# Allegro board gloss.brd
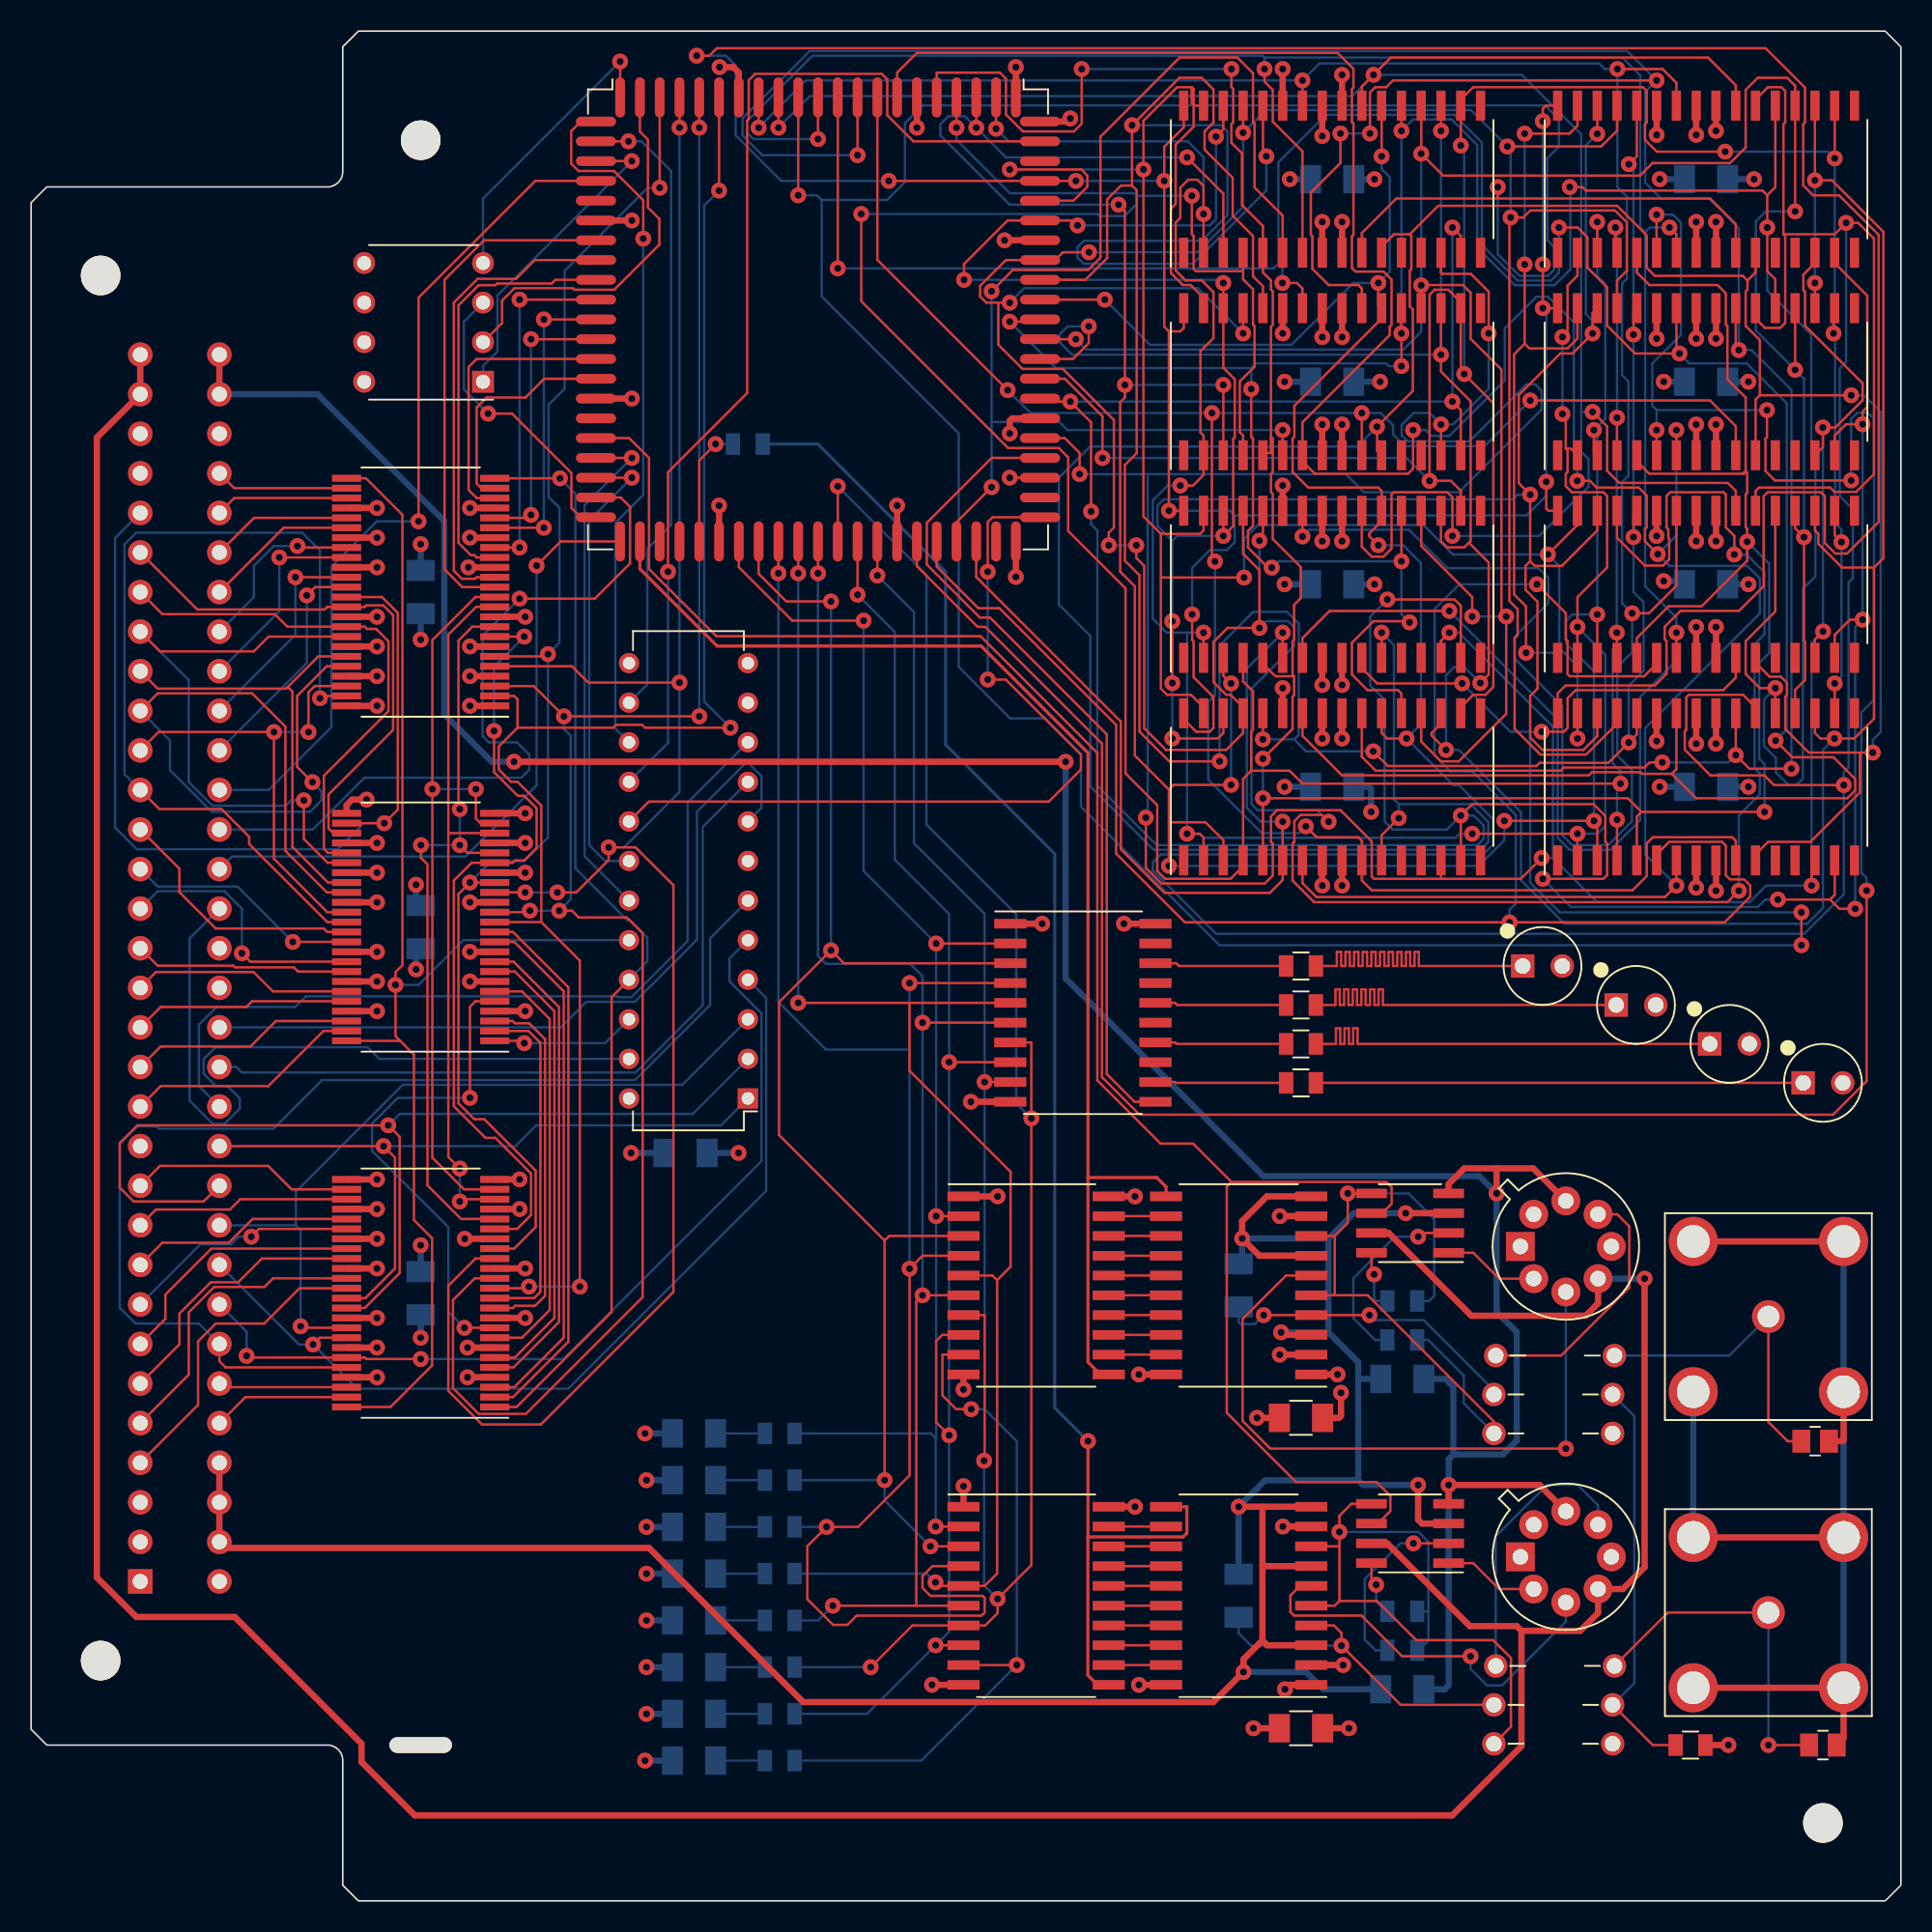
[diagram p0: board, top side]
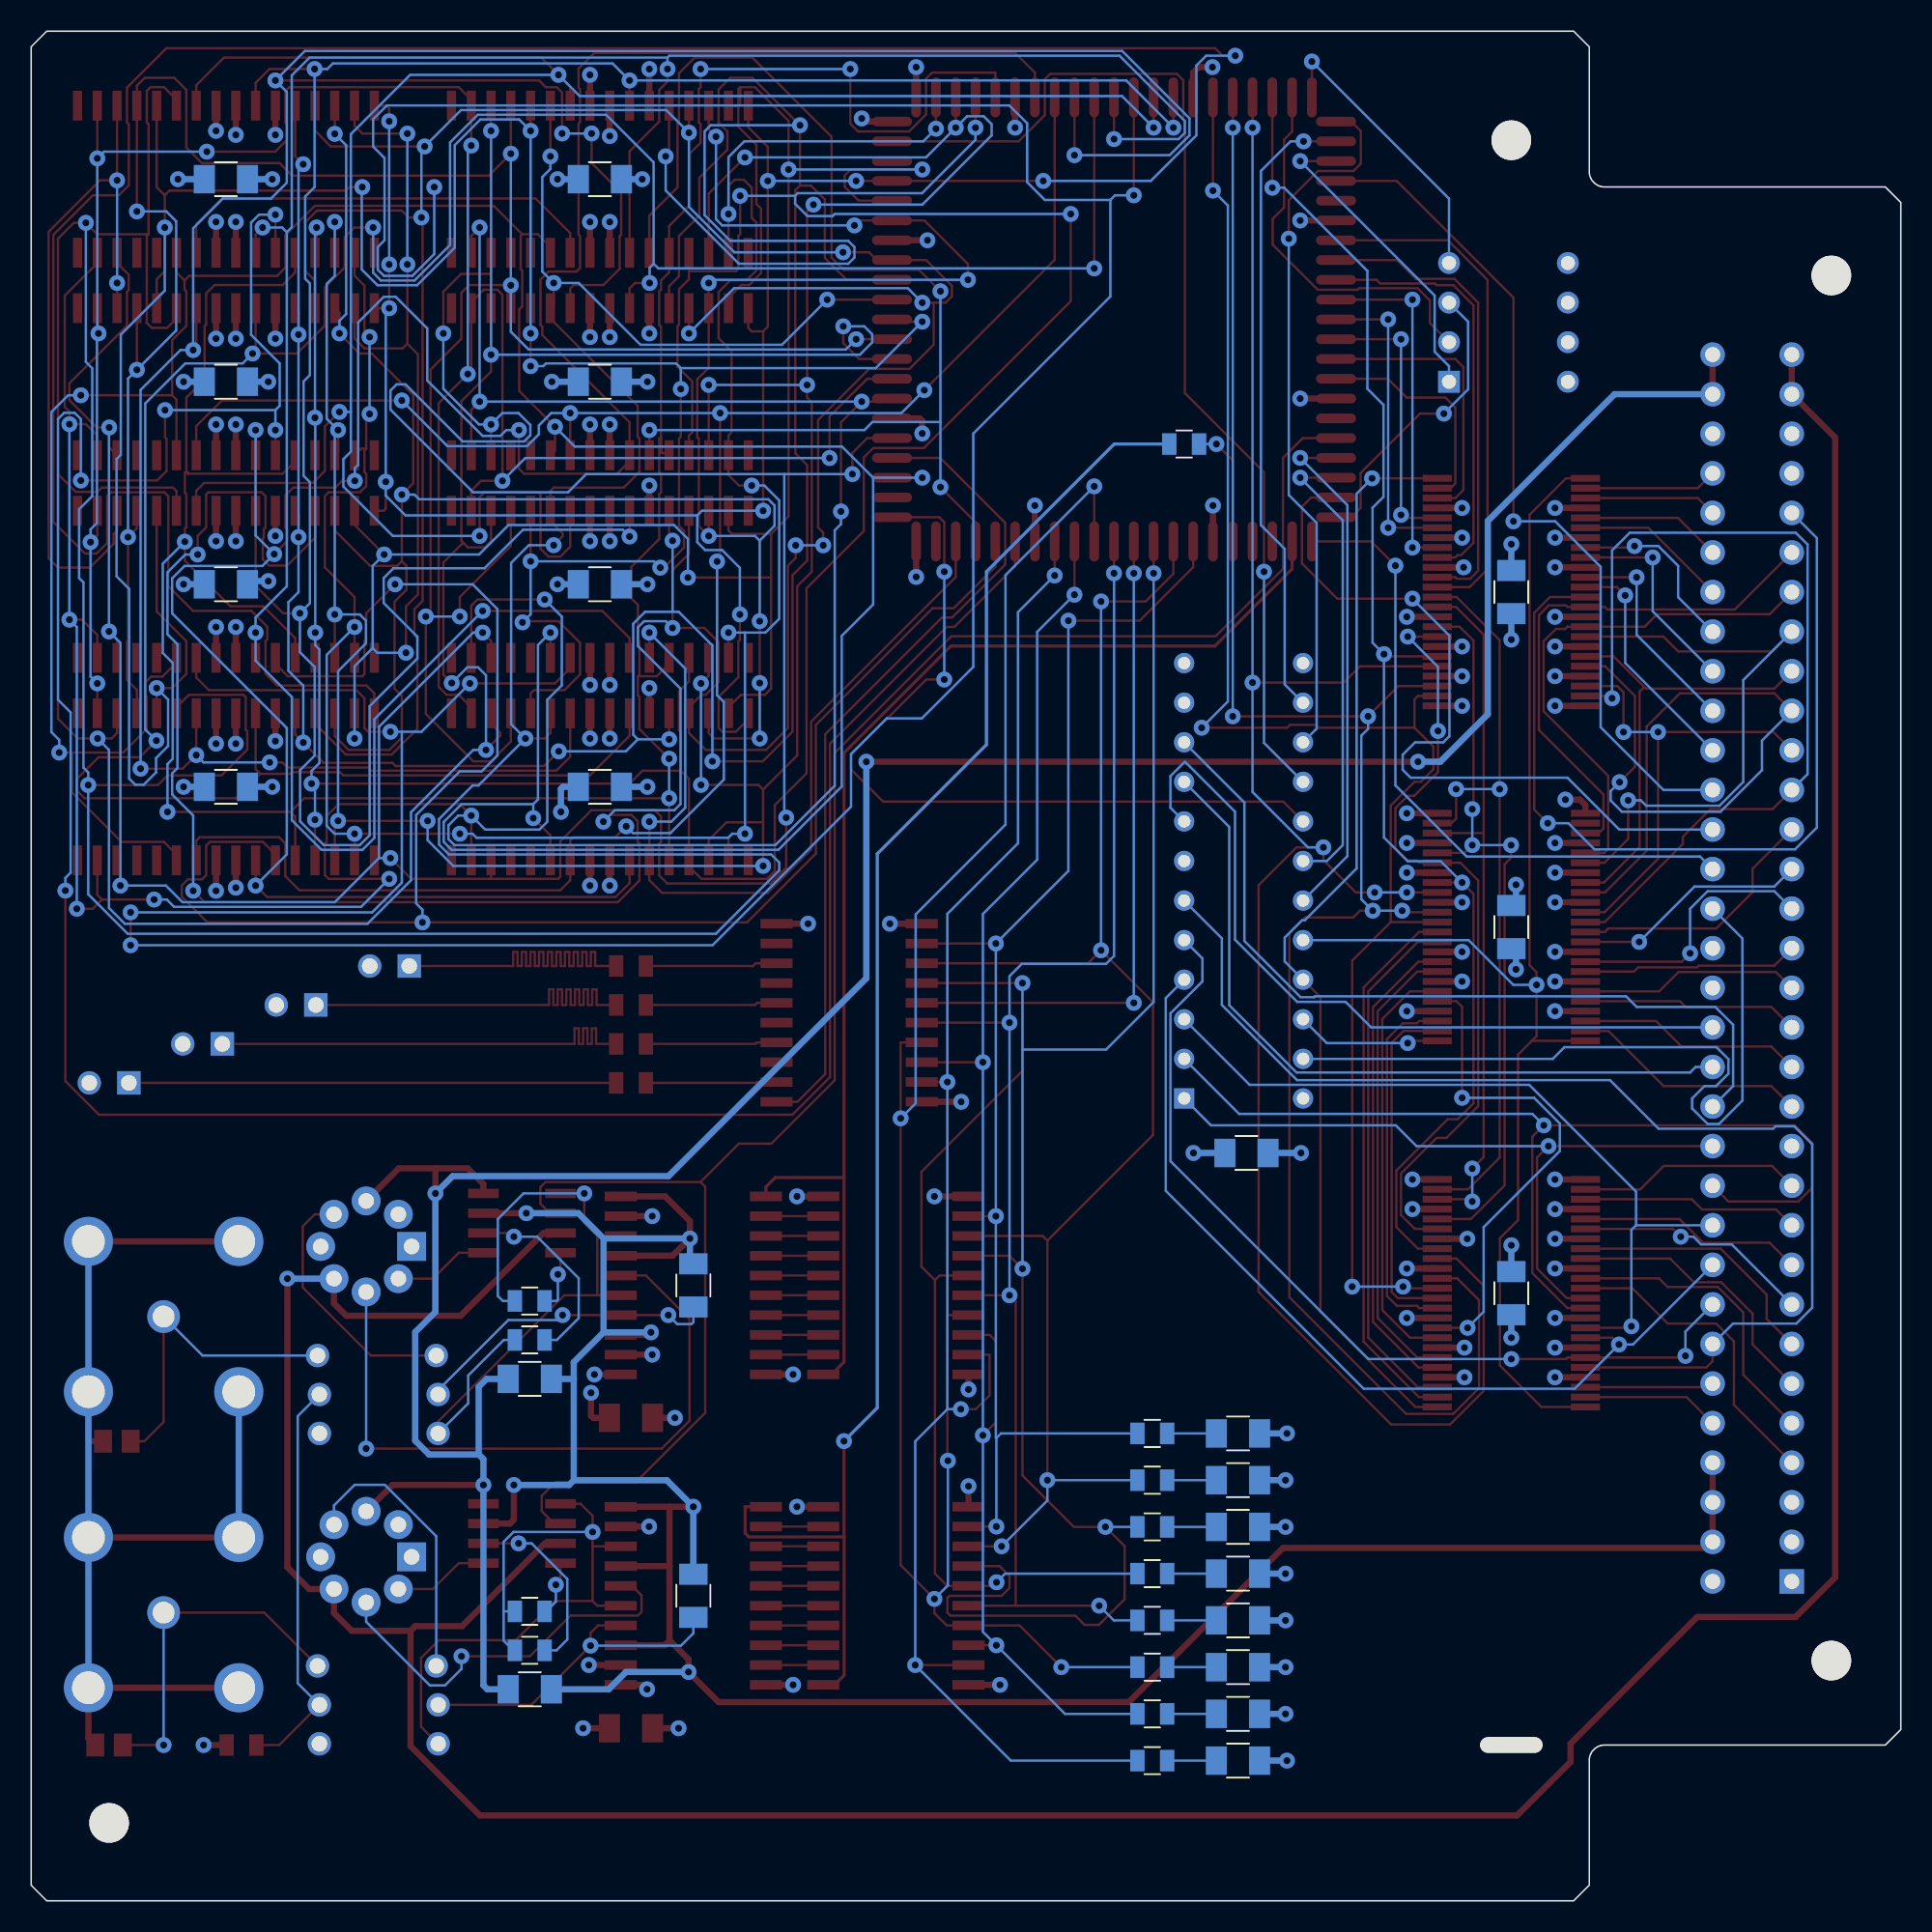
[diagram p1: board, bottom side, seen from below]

Outline 120 x 120 mm; copper layers: TOP, GND1, VCC1, VCC2, GND2, BOTTOM. Coordinates in mm from the lower left corner of the outline.

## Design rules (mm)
constraint set DEFAULT: min track width 0.15, pair gap 0.15
net group SYNC: nets VCLKA VCLKC
net group LEDNETS: nets LED1 LED2 LED3 LED4
net group MEMORY[0..28]: nets MEMORY.RA0 MEMORY.RA1 MEMORY.RA2 MEMORY.RA3 MEMORY.RA4 MEMORY.RA5 MEMORY.RA6 MEMORY.RA7 MEMORY.RA8 MEMORY.RA9 MEMORY.RA10 MEMORY.RA11 MEMORY.RA12 MEMORY.RA13 MEMORY.RA14 MEMORY.RA15 MEMORY.RCS0 MEMORY.RCS1 MEMORY.RCS2 MEMORY.RCS3 MEMORY.RD0 MEMORY.RD1 MEMORY.RD2 MEMORY.RD3 MEMORY.RD4 MEMORY.RD5 MEMORY.RD6 MEMORY.RD7 MEMORY.RWE
net group POWER: nets AGND GND_EARTH V12N V+12
net group VDNETS: nets VD0 VD1 VD2 VD3 VD4 VD5 VD6 VD7
nets with their own width: min track width 0.4; nets GND VCC

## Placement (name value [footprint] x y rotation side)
C1  0.1uF  [CAPC3216X110N]  25 39 90 bottom
C2  0.1uF  [CAPC3216X110N]  42 48 0 bottom
C3  0.1uF  [CAPC3216X110N]  25 62.5 90 bottom
C4  0.1uF  [CAPC3216X110N]  25 84 90 bottom
C5  47PF  [CAPC2012X110N]  114.5 29.5 0 top
C6  47PF  [CAPC2012X110N]  115 10 0 top
C7  0.01u  [CAPC3216X110N]  81.5 31 0 top
C8  0.01u  [CAPC3216X110N]  77.5 39.5 90 bottom
C9  0.1u  [CAPC3216X110N]  88 33.5 180 bottom
C10  0.01u  [CAPC3216X110N]  81.5 11.08 0 top
C11  0.01u  [CAPC3216X110N]  77.5 19.58 90 bottom
C12  0.1u  [CAPC3216X110N]  88 13.58 180 bottom
C13  330p  [CAPC3216X110N]  42.55 12 180 bottom
C14  330p  [CAPC3216X110N]  42.55 18 180 bottom
C15  330p  [CAPC3216X110N]  42.55 24 180 bottom
C16  330p  [CAPC3216X110N]  42.55 30 180 bottom
C17  330p  [CAPC3216X110N]  42.55 9 180 bottom
C18  330p  [CAPC3216X110N]  42.55 15 180 bottom
C19  330p  [CAPC3216X110N]  42.55 21 180 bottom
C20  330p  [CAPC3216X110N]  42.55 27 180 bottom
C21  0.1uF  [CAPC3216X110N]  83.5 71.5 0 bottom
C22  0.1uF  [CAPC3216X110N]  107.5 71.5 0 bottom
C23  0.1uF  [CAPC3216X110N]  83.5 84.5 0 bottom
C24  0.1uF  [CAPC3216X110N]  107.5 84.5 0 bottom
C25  0.1uF  [CAPC3216X110N]  83.5 97.5 0 bottom
C26  0.1uF  [CAPC3216X110N]  107.5 97.5 0 bottom
C27  0.1uF  [CAPC3216X110N]  107.5 110.5 0 bottom
C28  0.1uF  [CAPC3216X110N]  83.5 110.5 0 bottom
D1  LED  [LEDRD254W00D500H860P]  97 60 0 top
D2  LED  [LEDRD254W00D500H860P]  103 57.5 0 top
D3  LED  [LEDRD254W00D500H860P]  109 55 0 top
D4  LED  [LEDRD254W00D500H860P]  115 52.5 0 top
J1  CON64  [DIN64]  7 20.5 0 top
J2  BNC  [CONNEX_112659]  111.5 37.5 0 top
J3  BNC  [CONNEX_112659]  111.5 18.5 0 top
L1  47u  [INDAD762W79L381D254P]  94 35 0 top
L2  47u  [INDAD762W79L381D254P]  94 15.08 0 top
L3  47u  [INDAD762W79L381D254P]  101.5 32.5 180 top
L4  47u  [INDAD762W79L381D254P]  101.5 30 180 top
L5  47u  [INDAD762W79L381D254P]  101.5 12.58 180 top
L6  47u  [INDAD762W79L381D254P]  101.5 10.08 180 top
NOREF  -  []  23 0 90 top
NOREF#2  -  []  25 10 90 top
NOREF#3  -  []  25 10 90 top
NOREF#4  -  []  -74.06 -89.06 0 top
NOREF#5  -  []  25 10 0 top
NOREF#6  -  []  115 5 90 top
NOREF#7  -  []  192.64 154.78 0 top
NOREF#8  -  []  25 10 0 top
NOREF#9  -  []  25 10 90 top
NOREF#10  -  [unnamed#2]  25 10 0 top
NOREF#11  -  []  0 20.43 0 top
NOREF#12  -  []  20 6.38 0 top
NOREF#13  -  []  119.52 119.48 0 top
NOREF#14  -  []  19.78 110.37 0 top
R1  150  [RESC2012X60N]  81.5 60 0 top
R2  150  [RESC2012X60N]  81.5 57.5 0 top
R3  150  [RESC2012X60N]  81.5 55 0 top
R4  150  [RESC2012X60N]  81.5 52.5 0 top
R5  2K  [RESC2012X60N]  46 93.5 0 bottom
R6  100  [RESC2012X60N]  88 38.5 180 bottom
R7  100  [RESC2012X60N]  88 36 180 bottom
R8  100  [RESC2012X60N]  88 18.58 180 bottom
R9  100  [RESC2012X60N]  88 16.08 180 bottom
R10  10K  [RESC2012X60N]  48.05 12 0 bottom
R11  10K  [RESC2012X60N]  48.05 18 0 bottom
R12  10K  [RESC2012X60N]  48.05 24 0 bottom
R13  10K  [RESC2012X60N]  48.05 30 0 bottom
R14  10K  [RESC2012X60N]  48.05 9 0 bottom
R15  10K  [RESC2012X60N]  48.05 15 0 bottom
R16  10K  [RESC2012X60N]  48.05 21 0 bottom
R17  10K  [RESC2012X60N]  48.05 27 0 bottom
R18  10K  [RESC2012X60N]  106.5 10 0 top
U1  FCT16245  [SOP63P1035X279-48N]  25 39 90 top
U2  20L10  [DIP763W46P254L3204H508Q24P]  46 51.5 90 top
U3  FCT16245  [SOP63P1035X279-48N]  25 62.5 90 top
U4  FCT16245  [SOP63P1035X279-48N]  25 84 90 top
U5  EPF8282A_LCC  [PLCC127P3022X3022X457-84N]  50.5 101.5 270 top
U6  74ACT574  [SOIC127P1034X264-20N]  67.5 57 270 top
U7  EPC1064  [DIP763W46P254L991H419Q8P]  29 97.5 90 top
U8  TLC5602A  [SOIC127P1034X264-20N]  77.5 39.5 90 top
U9  TLE2037A  [TO292P469H584-8P]  98.5 42 0 top
U10  DG419AK  [SOIC127P600X175-8N]  88.5 43.5 90 top
U11  TLC5602A  [SOIC127P1034X264-20N]  77.5 19.58 90 top
U12  TLE2037A  [TO292P469H584-8P]  98.5 22.08 0 top
U13  DG419AK  [SOIC127P600X175-8N]  88.5 23.58 90 top
U14  74ACT574  [SOIC127P1034X264-20N]  64.5 39.5 270 top
U15  74ACT574  [SOIC127P1034X264-20N]  64.5 19.58 270 top
U16  TC55B4257  [SOIC127P1032X265-32N]  83.5 71.5 0 top
U17  TC55B4257  [SOIC127P1032X265-32N]  83.5 84.5 0 top
U18  TC55B4257  [SOIC127P1032X265-32N]  83.5 97.5 0 top
U19  TC55B4257  [SOIC127P1032X265-32N]  83.5 110.5 0 top
U20  TC55B4257  [SOIC127P1032X265-32N]  107.5 71.5 0 top
U21  TC55B4257  [SOIC127P1032X265-32N]  107.5 84.5 0 top
U22  TC55B4257  [SOIC127P1032X265-32N]  107.5 97.5 0 top
U23  TC55B4257  [SOIC127P1032X265-32N]  107.5 110.5 0 top

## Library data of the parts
C1-C4 C13-C20 = CAP NP
C5 C7-C9 = CAP NP: room: CHAN1
C6 C10-C12 = CAP NP: room: CHAN2
C21-C28 = CAP NP: room: MEM
D1-D4 = PHOTODIODE_0
J1 = CON64
J2 = BNC: room: CHAN1
J3 = BNC: room: CHAN2
L1 L3 L4 = INDUCTOR: room: CHAN1
L2 L5 L6 = INDUCTOR: room: CHAN2
R1-R4 = R: room: LED
R5 R10-R17 = R
R6 R7 = R: room: CHAN1
R8 R9 R18 = R: room: CHAN2
U1 U3 U4 = FCT16245
U2 = 20L10: alternate symbols: (T:SOIC24;B:SOIC24_PE)
U5 = EPF8282A/LCC
U6 = 74ACT574: room: LED
U7 = EPC1064
U8 = TLC5602A: room: CHAN1
U9 = TLE2037A: room: CHAN1
U10 = DG419AK: room: CHAN1
U11 = TLC5602A: room: CHAN2
U12 = TLE2037A: room: CHAN2
U13 = DG419AK: room: CHAN2
U14 = 74ACT574: room: CHAN1
U15 = 74ACT574: room: CHAN2
U16-U23 = TC55B4257: room: MEM

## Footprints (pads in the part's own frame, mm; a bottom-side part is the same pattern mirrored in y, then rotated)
CAPC2012X110N
  rect 1.15x1.47 smd: 1(-0.885,0) 2(0.885,0)
CAPC3216X110N
  rect 1.35x1.82 smd: 1(-1.385,0) 2(1.385,0)
CONNEX_112659
  round 2.1 hole 1.4: 1(0,0)
  round 3.15 hole 2.1: 2(-4.825,4.825) 3(4.825,4.825) 4(4.825,-4.825) 5(-4.825,-4.825)
DIN64
  round 2.54 hole 2.794 unplated: (-2.54,83.82) (-2.54,-5.08)
  rect 1.575x1.575 hole 0.965: 1(0,0)
  round 1.575 hole 0.965: 2(0,2.54) 3(0,5.08) 4(0,7.62) 5(0,10.16) 6(0,12.7) 7(0,15.24) 8(0,17.78) 9(0,20.32) 10(0,22.86) 11(0,25.4) 12(0,27.94) 13(0,30.48) 14(0,33.02) 15(0,35.56) 16(0,38.1) 17(0,40.64) 18(0,43.18) 19(0,45.72) 20(0,48.26) 21(0,50.8) 22(0,53.34) 23(0,55.88) 24(0,58.42) 25(0,60.96) 26(0,63.5) 27(0,66.04) 28(0,68.58) 29(0,71.12) 30(0,73.66) 31(0,76.2) 32(0,78.74) 33(5.08,0) 34(5.08,2.54) 35(5.08,5.08) 36(5.08,7.62) 37(5.08,10.16) 38(5.08,12.7) 39(5.08,15.24) 40(5.08,17.78) 41(5.08,20.32) 42(5.08,22.86) 43(5.08,25.4) 44(5.08,27.94) 45(5.08,30.48) 46(5.08,33.02) 47(5.08,35.56) 48(5.08,38.1) 49(5.08,40.64) 50(5.08,43.18) 51(5.08,45.72) 52(5.08,48.26) 53(5.08,50.8) 54(5.08,53.34) 55(5.08,55.88) 56(5.08,58.42) 57(5.08,60.96) 58(5.08,63.5) 59(5.08,66.04) 60(5.08,68.58) 61(5.08,71.12) 62(5.08,73.66) 63(5.08,76.2) 64(5.08,78.74)
DIP763W46P254L991H419Q8P
  rect 1.4x1.4 hole 0.9: 1(0,0)
  round 1.4 hole 0.9: 2(2.54,0) 3(5.08,0) 4(7.62,0) 5(7.62,7.63) 6(5.08,7.63) 7(2.54,7.63) 8(0,7.63)
DIP763W46P254L3204H508Q24P
  rect 1.3x1.3 hole 0.8: 1(0,0)
  round 1.3 hole 0.8: 2(2.54,0) 3(5.08,0) 4(7.62,0) 5(10.16,0) 6(12.7,0) 7(15.24,0) 8(17.78,0) 9(20.32,0) 10(22.86,0) 11(25.4,0) 12(27.94,0) 13(27.94,7.63) 14(25.4,7.63) 15(22.86,7.63) 16(20.32,7.63) 17(17.78,7.63) 18(15.24,7.63) 19(12.7,7.63) 20(10.16,7.63) 21(7.62,7.63) 22(5.08,7.63) 23(2.54,7.63) 24(0,7.63)
INDAD762W79L381D254P
  round 1.5 hole 1: 1(0,0) 2(7.62,0)
LEDRD254W00D500H860P
  round 1.5 hole 1: A(1.27,0)
  rect 1.5x1.5 hole 1: C(-1.27,0)
PLCC127P3022X3022X457-84N
  oval 2.57x0.62 smd: 1(-14.25,0) 2(-14.25,-1.27) 3(-14.25,-2.54) 4(-14.25,-3.81) 5(-14.25,-5.08) 6(-14.25,-6.35) 7(-14.25,-7.62) 8(-14.25,-8.89) 9(-14.25,-10.16) 10(-14.25,-11.43) 11(-14.25,-12.7) 33(14.25,-12.7) 34(14.25,-11.43) 35(14.25,-10.16) 36(14.25,-8.89) 37(14.25,-7.62) 38(14.25,-6.35) 39(14.25,-5.08) 40(14.25,-3.81) 41(14.25,-2.54) 42(14.25,-1.27) 43(14.25,0) 44(14.25,1.27) 45(14.25,2.54) 46(14.25,3.81) 47(14.25,5.08) 48(14.25,6.35) 49(14.25,7.62) 50(14.25,8.89) 51(14.25,10.16) 52(14.25,11.43) 53(14.25,12.7) 75(-14.25,12.7) 76(-14.25,11.43) 77(-14.25,10.16) 78(-14.25,8.89) 79(-14.25,7.62) 80(-14.25,6.35) 81(-14.25,5.08) 82(-14.25,3.81) 83(-14.25,2.54) 84(-14.25,1.27)
  oval 0.62x2.57 smd: 12(-12.7,-14.25) 13(-11.43,-14.25) 14(-10.16,-14.25) 15(-8.89,-14.25) 16(-7.62,-14.25) 17(-6.35,-14.25) 18(-5.08,-14.25) 19(-3.81,-14.25) 20(-2.54,-14.25) 21(-1.27,-14.25) 22(0,-14.25) 23(1.27,-14.25) 24(2.54,-14.25) 25(3.81,-14.25) 26(5.08,-14.25) 27(6.35,-14.25) 28(7.62,-14.25) 29(8.89,-14.25) 30(10.16,-14.25) 31(11.43,-14.25) 32(12.7,-14.25) 54(12.7,14.25) 55(11.43,14.25) 56(10.16,14.25) 57(8.89,14.25) 58(7.62,14.25) 59(6.35,14.25) 60(5.08,14.25) 61(3.81,14.25) 62(2.54,14.25) 63(1.27,14.25) 64(0,14.25) 65(-1.27,14.25) 66(-2.54,14.25) 67(-3.81,14.25) 68(-5.08,14.25) 69(-6.35,14.25) 70(-7.62,14.25) 71(-8.89,14.25) 72(-10.16,14.25) 73(-11.43,14.25) 74(-12.7,14.25)
RESC2012X60N
  rect 0.92x1.38 smd: 1(-0.955,0) 2(0.955,0)
SOIC127P600X175-8N
  rect 0.6x1.97 smd: 1(-1.905,-2.475) 2(-0.635,-2.475) 3(0.635,-2.475) 4(1.905,-2.475) 5(1.905,2.475) 6(0.635,2.475) 7(-0.635,2.475) 8(-1.905,2.475)
SOIC127P1032X265-32N
  rect 0.59x1.92 smd: 1(-9.525,-4.72) 2(-8.255,-4.72) 3(-6.985,-4.72) 4(-5.715,-4.72) 5(-4.445,-4.72) 6(-3.175,-4.72) 7(-1.905,-4.72) 8(-0.635,-4.72) 9(0.635,-4.72) 10(1.905,-4.72) 11(3.175,-4.72) 12(4.445,-4.72) 13(5.715,-4.72) 14(6.985,-4.72) 15(8.255,-4.72) 16(9.525,-4.72) 17(9.525,4.72) 18(8.255,4.72) 19(6.985,4.72) 20(5.715,4.72) 21(4.445,4.72) 22(3.175,4.72) 23(1.905,4.72) 24(0.635,4.72) 25(-0.635,4.72) 26(-1.905,4.72) 27(-3.175,4.72) 28(-4.445,4.72) 29(-5.715,4.72) 30(-6.985,4.72) 31(-8.255,4.72) 32(-9.525,4.72)
SOIC127P1034X264-20N
  rect 0.61x2.06 smd: 1(-5.715,-4.66) 2(-4.445,-4.66) 3(-3.175,-4.66) 4(-1.905,-4.66) 5(-0.635,-4.66) 6(0.635,-4.66) 7(1.905,-4.66) 8(3.175,-4.66) 9(4.445,-4.66) 10(5.715,-4.66) 11(5.715,4.66) 12(4.445,4.66) 13(3.175,4.66) 14(1.905,4.66) 15(0.635,4.66) 16(-0.635,4.66) 17(-1.905,4.66) 18(-3.175,4.66) 19(-4.445,4.66) 20(-5.715,4.66)
SOP63P1035X279-48N
  rect 0.44x1.87 smd: 1(-7.302,-4.755) 2(-6.668,-4.755) 3(-6.032,-4.755) 4(-5.398,-4.755) 5(-4.762,-4.755) 6(-4.128,-4.755) 7(-3.492,-4.755) 8(-2.858,-4.755) 9(-2.222,-4.755) 10(-1.588,-4.755) 11(-0.952,-4.755) 12(-0.318,-4.755) 13(0.318,-4.755) 14(0.952,-4.755) 15(1.588,-4.755) 16(2.222,-4.755) 17(2.858,-4.755) 18(3.492,-4.755) 19(4.128,-4.755) 20(4.762,-4.755) 21(5.398,-4.755) 22(6.032,-4.755) 23(6.668,-4.755) 24(7.302,-4.755) 25(7.302,4.755) 26(6.668,4.755) 27(6.032,4.755) 28(5.398,4.755) 29(4.762,4.755) 30(4.128,4.755) 31(3.492,4.755) 32(2.858,4.755) 33(2.222,4.755) 34(1.588,4.755) 35(0.952,4.755) 36(0.318,4.755) 37(-0.318,4.755) 38(-0.952,4.755) 39(-1.588,4.755) 40(-2.222,4.755) 41(-2.858,4.755) 42(-3.492,4.755) 43(-4.128,4.755) 44(-4.762,4.755) 45(-5.398,4.755) 46(-6.032,4.755) 47(-6.668,4.755) 48(-7.302,4.755)
TO292P469H584-8P
  rect 1.85x1.85 hole 1: 1(-2.921,0)
  round 1.85 hole 1: 2(-2.066,-2.066) 3(0,-2.921) 4(2.066,-2.066) 5(2.921,0) 6(2.066,2.066) 7(0,2.921) 8(-2.066,2.066)
unnamed#2
  round 2.54 hole 2.794 unplated: (0,103) (90,-5)
  oval 4x1 hole 5x1.5 unplated: (0,0)

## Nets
AGND: C8.2 C9.2 C11.2 C12.2 J1.34 J1.35 J1.36 U8.3 U8.7 U8.10 U10.3 U11.3 U11.7 U11.10 U13.3
GND: C1.2 C2.2 C3.2 C4.2 C7.2 C10.2 C13.2 C14.2 C15.2 C16.2 C17.2 C18.2 C19.2 C20.2 C21.2 C22.2 C23.2 C24.2 C25.2 C26.2 C27.2 C28.2 J1.1 J1.2 J1.3 J1.33 R18.2 U1.4 U1.10 U1.15 U1.21 U1.24 U1.25(G\) U1.28 U1.34 U1.39 U1.45 U2.11 U2.12 U2.13 U3.4 U3.10 U3.15 U3.21 U3.24 U3.25(G\) U3.28 U3.34 U3.39 U3.45 U4.1 U4.4 U4.10 U4.15 U4.21 U4.28 U4.34 U4.39 U4.45 U4.48 U5.5 U5.26 U5.47 U5.53 U5.68 U5.74 U5.75 U6.1 U6.10 U7.5 U8.1 U8.20 U11.1 U11.20 U14.1 U14.10 U15.1 U15.10 U16.9 U16.25 U16.27 U17.9 U17.25 U17.27 U18.9 U18.25 U18.27 U19.9 U19.25 U19.27 U20.9 U20.25 U20.27 U21.9 U21.25 U21.27 U22.9 U22.25 U22.27 U23.9 U23.25 U23.27
GND_EARTH: C5.2 C6.2 J2.2 J2.3 J2.4 J2.5(GND5) J3.2 J3.3 J3.4 J3.5(GND5)
V12N: J1.31 J1.32 U9.4(V-) U10.7 U12.4(V-) U13.7
VCC: C1.1 C2.1 C3.1 C4.1 C7.1 C10.1 C21.1 C22.1 C23.1 C24.1 C25.1 C26.1 C27.1 C28.1 D1.A D2.A D3.A D4.A J1.29 J1.30 J1.62 L4.1 L6.1 U1.7 U1.18 U1.31 U1.42 U2.24(VCC) U3.7 U3.18 U3.31 U3.42 U4.7 U4.18 U4.31 U4.42 U5.17 U5.38 U5.59 U5.80 U6.20 U7.7 U7.8 U8.2 U8.9(VD2) U11.2 U11.9(VD2) U14.20 U15.20 U16.8 U16.24 U17.8 U17.24 U18.8 U18.24 U19.8 U19.24 U20.8 U20.24 U21.8 U21.24 U22.8 U22.24 U23.8 U23.24
A0: J1.54 U4.36
A1: J1.55 U4.35
A2: J1.56 U4.33
A3: J1.57 U4.32
A4: J1.58 U4.30
A5: J1.59 U4.29
A6: J1.60 U4.27
A7: J1.61 U4.26
A8: J1.13 U3.47
A9: J1.14 U3.46
A10: J1.15 U3.44
A11: J1.16 U3.43
A12: J1.17 U3.41
A13: J1.18 U3.40
A14: J1.19 U3.38
A15: J1.20 U3.37
A16: J1.37 U1.47
A17: J1.38 U1.46
A18: J1.39 U1.44 U2.6
A19: J1.40 U1.43 U2.5
A20: J1.41 U1.41 U2.4
A21: J1.42 U1.40 U2.3
A22: J1.43 U1.38 U2.2
A23: J1.44 U1.37 U2.1
AEN: J1.47 U2.8
BA0: U1.13 U3.13 U4.2 U5.6
BA1: U1.14 U3.14 U4.3 U5.7
BA2: U1.16 U3.16 U4.5 U5.8
BA3: U1.17 U3.17 U4.6 U5.9
BA4: U1.19 U3.19 U4.8
BA5: U1.20 U3.20 U4.9
BA6: U1.22 U3.22 U4.11
BA7: U1.23 U3.23 U4.12
BD0: U4.23 U5.25
BD1: U4.22 U5.24
BD2: U4.20 U5.23
BD3: U4.19 U5.22
BD4: U4.17 U5.21
BD5: U4.16 U5.20
BD6: U4.14 U5.19
BD7: U4.13 U5.18
BD8: U1.12 U3.2
BD9: U1.11 U3.3
BD10: U1.9 U3.5
BD11: U1.8 U3.6
BD12: U1.6 U3.8
BD13: U1.5 U3.9
BD14: U1.3 U3.11
BD15: U1.2 U3.12
BNC2: C5.1 J2.1 L1.2
BNC3: C6.1 J3.1 L2.2
BRD: U2.16 U5.73
BRESET: U2.15 U5.12
BWR: U2.17 U5.54
D0: J1.28 U3.26 U4.37
D1: J1.27 U3.27 U4.38
D2: J1.26 U3.29 U4.40
D3: J1.25 U3.30 U4.41
D4: J1.24 U3.32 U4.43
D5: J1.23 U3.33 U4.44
D6: J1.22 U3.35 U4.46
D7: J1.21 U3.36 U4.47
D8: J1.4 U1.36
D9: J1.5 U1.35
D10: J1.6 U1.33
D11: J1.7 U1.32
D12: J1.8 U1.30
D13: J1.9 U1.29
D14: J1.10 U1.27
D15: J1.11 U1.26
DATA: U5.14 U7.1
DCLK: U5.10 U7.2
DDIR: U1.48 U2.20 U3.48 U4.25(G\)
DEN: U1.1 U2.21 U4.24
DHEN: U2.22 U3.1
FPGA: U2.18 U5.30
GAIN: U5.28 U10.6 U13.6
HS: U2.19 U5.29
LED1: D1.C(CATHODE) R1.2
LED2: D2.C(CATHODE) R2.2
LED3: D3.C(CATHODE) R3.2
LED4: D4.C(CATHODE) R4.2
MCLK: J1.52 U5.31
MEMORY.RA0: U5.79 U16.5 U17.5 U18.5 U19.5 U20.5 U21.5 U22.5 U23.5
MEMORY.RA1: U5.78 U16.4 U17.4 U18.4 U19.4 U20.4 U21.4 U22.4 U23.4
MEMORY.RA2: U5.77 U16.3 U17.3 U18.3 U19.3 U20.3 U21.3 U22.3 U23.3
MEMORY.RA3: U5.76 U16.2 U17.2 U18.2 U19.2 U20.2 U21.2 U22.2 U23.2
MEMORY.RA4: U5.71 U16.32 U17.32 U18.32 U19.32 U20.32 U21.32 U22.32 U23.32
MEMORY.RA5: U5.70 U16.31 U17.31 U18.31 U19.31 U20.31 U21.31 U22.31 U23.31
MEMORY.RA6: U5.69 U16.30 U17.30 U18.30 U19.30 U20.30 U21.30 U22.30 U23.30
MEMORY.RA7: U5.67 U16.29 U17.29 U18.29 U19.29 U20.29 U21.29 U22.29 U23.29
MEMORY.RA8: U5.66 U16.28 U17.28 U18.28 U19.28 U20.28 U21.28 U22.28 U23.28
MEMORY.RA9: U5.65 U16.22 U17.22 U18.22 U19.22 U20.22 U21.22 U22.22 U23.22
MEMORY.RA10: U5.64 U16.21 U17.21 U18.21 U19.21 U20.21 U21.21 U22.21 U23.21
MEMORY.RA11: U5.63 U16.20 U17.20 U18.20 U19.20 U20.20 U21.20 U22.20 U23.20
MEMORY.RA12: U5.62 U16.19 U17.19 U18.19 U19.19 U20.19 U21.19 U22.19 U23.19
MEMORY.RA13: U5.61 U16.18 U17.18 U18.18 U19.18 U20.18 U21.18 U22.18 U23.18
MEMORY.RA14: U5.60 U16.15 U17.15 U18.15 U19.15 U20.15 U21.15 U22.15 U23.15
MEMORY.RA15: U5.58 U16.14 U17.14 U18.14 U19.14 U20.14 U21.14 U22.14 U23.14
MEMORY.RCS0: U5.51 U16.6 U17.6
MEMORY.RCS1: U5.50 U18.6 U19.6
MEMORY.RCS2: U5.49 U20.6 U21.6
MEMORY.RCS3: U5.48 U22.6 U23.6
MEMORY.RD0: U5.81 U16.7 U18.7 U20.7 U22.7
MEMORY.RD1: U5.82 U16.10 U18.10 U20.10 U22.10
MEMORY.RD2: U5.83 U16.23 U18.23 U20.23 U22.23
MEMORY.RD3: U5.84 U16.26 U18.26 U20.26 U22.26
MEMORY.RD4: U5.1 U17.7 U19.7 U21.7 U23.7
MEMORY.RD5: U5.2 U17.10 U19.10 U21.10 U23.10
MEMORY.RD6: U5.3 U17.23 U19.23 U21.23 U23.23
MEMORY.RD7: U5.4 U17.26 U19.26 U21.26 U23.26
MEMORY.RWE: U5.56 U16.11(W\E\) U17.11(W\E\) U18.11(W\E\) U19.11(W\E\) U20.11(W\E\) U21.11(W\E\) U22.11(W\E\) U23.11(W\E\)
MRD: J1.46 U2.9
MWR: J1.45 U2.10
N00036_DATA_DAAMP: L4.2 R6.1 R7.1 U8.5 U8.8 U10.5(VL)
N00036_DATA_DAAMP1: L6.2 R8.1 R9.1 U11.5 U11.8 U13.5(VL)
N00038_DATA_DAAMP: C8.1 L3.2 U8.4
N00038_DATA_DAAMP1: C11.1 L5.2 U11.4
N00044_DATA_DAAMP: U9.2 U10.1
N00044_DATA_DAAMP1: U12.2 U13.1
N00060_DATA_DAAMP: U8.6 U9.3
N00060_DATA_DAAMP1: U11.6 U12.3
N282866_DATA_DAAMP: R6.2 U10.8
N282866_DATA_DAAMP1: R8.2 U13.8
N282912_DATA_DAAMP: R7.2 U10.2
N282912_DATA_DAAMP1: R9.2 U13.2
NCS: U5.11 U7.4
OE: U5.32 U7.3(OE)
OUTA: L1.1 U9.6
OUTB: L2.1 U12.6
Q0: R1.1 U6.18
Q1: R2.1 U6.16
Q2: R3.1 U6.14
Q3: R4.1 U6.12(Q8)
RDY: J1.50 U2.23
RESET: J1.53 U5.15
SEL: U2.14 U5.13
V+12: C9.1 C12.1 J1.63 J1.64 U9.7 U10.4 U12.7 U13.4
VCLKA: U5.34 U8.11 U14.11
VCLKC: R5.2 U11.11 U15.11
VD0: R13.2 U5.39 U6.2 U14.2 U15.2
VD1: R17.2 U5.40 U6.3 U14.3 U15.3
VD2: R12.2 U5.41 U6.4 U14.4 U15.4
VD3: R16.2 U5.42 U6.5 U14.5 U15.5
VD4: R11.2 U5.43 U6.6 U14.6 U15.6
VD5: R15.2 U5.44 U6.7 U14.7 U15.7
VD6: R10.2 U5.45 U6.8 U14.8 U15.8
VD7: R14.2 U5.46(VD7) U6.9 U14.9 U15.9
VREF: L3.1 L5.1 R18.1
WAIT: J1.51 U5.33
WSTAT: U5.57 U6.11
N14843: C19.1 R16.1
N14849: C15.1 R12.1
N14853: C20.1 R17.1
N14855: C16.1 R13.1
N15143: C17.1 R14.1
N15151: C13.1 R10.1
N15155: C18.1 R15.1
N15161: C14.1 R11.1
N58063: U8.12 U14.19
N58118: U8.13 U14.18
N58173: U8.14 U14.17
N58228: U8.15 U14.16
N58283: U8.16 U14.15
N58338: U8.17 U14.14
N58393: U8.18 U14.13
N58448: U8.19 U14.12(Q8)
N58834: U11.12 U15.19
N58889: U11.13 U15.18
N58944: U11.14 U15.17
N58999: U11.15 U15.16
N59054: U11.16 U15.15
N59109: U11.17 U15.14
N59164: U11.18 U15.13
N59219: U11.19 U15.12(Q8)
N409523: R5.1 U5.37

Pads without a net: J1 12 48 49; U2 7; U5 16 27 35 36 52 55 72; U6 13 15 17 19; U7 6; U9 1 5 8; U12 1 5 8; U16 1 12 13 16 17; U17 1 12 13 16 17; U18 1 12 13 16 17; U19 1 12 13 16 17; U20 1 12 13 16 17; U21 1 12 13 16 17; U22 1 12 13 16 17; U23 1 12 13 16 17

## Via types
v1: diameter 1.016, hole 0.457, TOP to BOTTOM, 486 vias

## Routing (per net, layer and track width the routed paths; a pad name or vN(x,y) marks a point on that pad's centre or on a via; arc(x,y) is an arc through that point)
AGND: length 177.8
  TOP w0.4: 79.03,16.7 79.01,16.7 77.81,15.5 v1(77.81,14.69) 75.88,12.76 49.55,12.76 39.65,22.65 12.47,22.65 J1.34 J1.35 J1.36 ; 79.03,16.7 79.33,16.4 U11.3 ; 79.03,16.7 79.03,21.48 ; U11.10 79.03,25.29 ; 79.03,25.29 79.03,21.48 ; 79.03,25.29 v1(77.5,25.29) ; U8.10 79.31,45.22 77.72,43.63 v1(77.72,42.51) 78.83,41.41 U8.7 ; v1(80.22,36.49) 80.38,36.33 U8.3 ; U13.3 89.27,24.21 89.02,24.47 v1(89.02,26.69) ; 79.03,21.48 U11.7 ; U10.3 v1(88.22,44.13)
  BOTTOM w0.4: 83.26,42.51 84.88,44.13 v1(88.22,44.13) ; 83.26,42.51 83.26,36.49 ; 83.26,42.51 v1(77.72,42.51) 77.72,41.11 C8.2 ; C12.2 82.93,13.58 81.83,14.69 v1(77.81,14.69) ; C11.2 v1(77.5,25.29) 79.2,26.99 85.17,26.99 ; 85.17,26.99 85.47,26.69 v1(89.02,26.69) ; 85.17,26.99 85.17,33.5 ; 85.17,33.5 85.17,34.57 83.26,36.49 ; 85.17,33.5 C9.2 ; v1(80.22,36.49) 83.26,36.49
GND: length 231.4
  TOP w0.4: U3.4 v1(31.71,57.1) ; U1.15 v1(31.71,40.59) ; U15.10 v1(57.82,13.86) ; U21.25 v1(106.86,87.27) ; U3.39 v1(22.2,60.91) ; U5.68 v1(62.47,106.58) ; U6.1 v1(64.89,62.72) ; C10.2 v1(84.58,11.08) ; U4.45 v1(22.2,78.6) ; C7.2 83.93,31 84.07,31.14 v1(84.07,32.61) ; U4.39 v1(22.2,82.41) ; U5.47 v1(55.58,89.55) ; U3.45 v1(22.2,57.1) ; U17.9 v1(84.13,78.04) ; U17.25 v1(82.87,87.27) ; U23.25 v1(106.86,113.34) ; U5.26 v1(38.55,96.42) ; U3.10 v1(28.16,60.91) ; U11.1 80.76,13.86 v1(80.47,13.58) ; U23.9 v1(108.14,107.76) ; U22.25 v1(106.86,100.27) ; U8.20 v1(71.1,33.78) ; U4.4 v1(28.16,78.6) ; U3.28 v1(22.2,67.9) ; U1.28 v1(22.2,44.4) ; U16.9 v1(84.13,65.16) ; U3.34 v1(22.2,64.09) ; U1.45 v1(22.2,33.6) ; U3.21 v1(31.71,67.9) ; U22.9 v1(108.14,94.76) ; U18.27 v1(80.33,100.6) ; U4.48 v1(22.2,76.7) ; U17.27 v1(80.33,90.84) ; U4.28 v1(22.2,89.4) ; U23.27 v1(104.33,113.34) ; 20.25,69.8 20.25,70.33 20.6,70.68 v1(21.53,70.68) ; U1.39 v1(22.2,37.41) ; U4.34 v1(22.2,85.59) ; R18.2 v1(108.93,10) ; U1.24 v1(31.35,46.3) ; U6.10 v1(60.31,51.28) ; U22.27 v1(104.33,100.27) ; U20.9 v1(108.14,64.83) ; U20.25 v1(106.86,74.27) ; U20.27 v1(104.33,74.43) ; U5.53 v1(63.2,84.97) ; U21.27 v1(104.33,87.6) ; U5.5 45.42,117.34 45.07,117.69 v1(44.18,117.69) ; U3.15 v1(28.16,64.09) ; U5.75 v1(63.2,117.69) ; U1.34 v1(22.2,40.59) ; 20.25,46.3 v1(22.2,46.3) ; U18.9 v1(84.13,94.76) ; U1.21 v1(31.35,44.4) ; U11.20 v1(71.1,13.86) ; U1.10 v1(31.71,37.41) ; U4.15 v1(28.06,85.59) ; U14.10 v1(59.84,32.82) ; U16.25 v1(82.87,74.6) ; U18.25 v1(82.87,100.37) ; U5.74 66.5,114.2 v1(66.69,114.4) ; U3.24 v1(31.71,69.8) ; U15.1 v1(59.84,26.62) ; U4.10 v1(31.71,82.41) ; U21.9 v1(108.14,81.76) ; U4.21 v1(28.16,89.4) ; U14.1 v1(62.03,45.22) ; 29.75,76.7 v1(28.16,76.7) ; U19.27 v1(80.33,117.57) ; U16.27 v1(80.33,77.84) ; U8.1 v1(83.85,33.78) ; U19.25 v1(82.87,113.27) ; U19.9 v1(84.13,107.76) ; U1.4 v1(28.01,33.6)
  GND1 w0.4: J1.3 7,26.55 ; J1.3 6.03,25.58 ; J1.3 7,24.61 ; J1.3 7.97,25.58 ; U2.11 46.83,76.9 ; U2.11 46,77.73 ; U2.11 46,76.07 ; U2.11 45.17,76.9 ; J1.2 7.97,23.04 ; J1.2 7,24.01 ; J1.2 6.03,23.04 ; J1.2 7,22.07 ; 11.11,20.5 J1.33 ; J1.33 12.08,21.47 ; J1.33 13.05,20.5 ; J1.33 12.08,19.53 ; 6.03,20.5 J1.1 ; J1.1 7,21.47 ; J1.1 7,19.53 ; J1.1 7.97,20.5 ; 21.37,104.24 U7.5 ; U7.5 20.49,105.12 ; U7.5 21.37,106 ; U7.5 22.25,105.12 ; U2.13 38.37,80.27 ; U2.13 37.54,79.44 ; U2.13 39.2,79.44 ; U2.13 38.37,78.61 ; U2.12 46.83,79.44 ; U2.12 46,80.27 ; U2.12 45.17,79.44 ; U2.12 46,78.61
  GND2 w0.4: 7,22.07 J1.2 ; J1.2 7,24.01 ; J1.2 6.03,23.04 ; J1.2 7.97,23.04 ; U7.5 22.25,105.12 ; U7.5 21.37,104.24 ; U7.5 20.49,105.12 ; U7.5 21.37,106 ; 6.03,20.5 J1.1 ; J1.1 7,21.47 ; J1.1 7.97,20.5 ; J1.1 7,19.53 ; U2.11 46,77.73 ; U2.11 46,76.07 ; U2.11 46.83,76.9 ; U2.11 45.17,76.9 ; 11.11,20.5 J1.33 ; J1.33 12.08,21.47 ; J1.33 12.08,19.53 ; J1.33 13.05,20.5 ; U2.13 38.37,80.27 ; U2.13 38.37,78.61 ; U2.13 37.54,79.44 ; U2.13 39.2,79.44 ; 46,78.61 U2.12 ; U2.12 46.83,79.44 ; U2.12 46,80.27 ; U2.12 45.17,79.44 ; J1.3 7,26.55 ; J1.3 6.03,25.58 ; J1.3 7.97,25.58 ; J1.3 7,24.61
  BOTTOM w0.4: C26.2 v1(110.22,97.5) ; C16.2 v1(39.4,30) ; C25.2 v1(86.58,97.5) ; C3.2 24.7,64.18 v1(24.7,65.22) ; C22.2 v1(110.22,71.5) ; C2.2 v1(45.4,48) ; C28.2 v1(86.22,110.5) ; C15.2 v1(39.49,24) ; C21.2 85.87,71.5 86,71.37 v1(86,69.89) ; C18.2 v1(39.49,15) ; C14.2 v1(39.49,18) ; C4.2 v1(25,87.08) ; C23.2 v1(86.22,84.5) ; C17.2 v1(39.4,9) ; C24.2 v1(110.22,84.5) ; C20.2 v1(39.49,27) ; C1.2 v1(25,42.08) ; C13.2 v1(39.49,12) ; C19.2 v1(39.49,21) ; C27.2 v1(110.58,110.5)
GND_EARTH: length 74.9
  TOP w0.4: C5.2 116.27,29.5 116.33,29.56 J2.4 ; J2.2 J2.3 ; J3.3 J3.2 ; J3.5 J3.4 116.33,10.44 C6.2
  BOTTOM w0.4: J2.3 J2.4 J3.3 J3.4 ; J2.5 J3.2
V12N: length 249.9
  TOP w0.4: v1(103.55,39.93) 103.55,21.41 102.16,20.01 100.57,20.01 100.57,18.48 99.42,17.33 95.65,17.33 ; 95.65,17.33 95.35,17.63 92.34,17.63 87.03,22.94 U13.7 ; 95.65,17.33 95.65,9.93 91.2,5.48 24.63,5.48 21.2,8.91 21.2,10.09 13.07,18.22 6.75,18.22 4.21,20.76 4.21,93.91 J1.31 J1.32 ; U9.4 100.57,38.35 99.77,37.55 92.44,37.55 87.12,42.87 U10.7
  BOTTOM w0.4: v1(103.55,39.93) U9.4
VCC: length 185.3
  TOP w0.4: U8.9 v1(80.14,43.95) ; U4.7 v1(28.16,80.51) ; U4.42 v1(22.2,80.51) ; U5.17 v1(38.55,107.85) ; U23.8 v1(106.86,107.76) ; U1.7 v1(28.01,35.51) ; U4.31 v1(22.2,87.49) ; U21.24 v1(108.14,87.27) ; U1.42 v1(22.2,35.51) ; U22.24 v1(108.14,100.27) ; U5.59 62.96,95.15 62.81,94.99 v1(62.81,94.18) ; U5.80 v1(56.85,113.81) ; U1.31 v1(22.2,42.49) ; U20.24 v1(108.14,74.27) ; U17.8 v1(82.87,78.04) ; C10.1 v1(78.45,11.08) ; U3.42 v1(22.2,59.01) ; U14.20 v1(70.85,45.22) ; U3.7 v1(28.16,59.01) ; U3.18 v1(31.71,65.99) ; U6.20 v1(70.14,62.72) ; U8.2 v1(80.14,35.05) ; U20.8 v1(106.86,65.03) ; U15.20 v1(70.85,25.29) ; U11.9 v1(80.34,24.02) ; U22.8 v1(106.86,94.76) ; U18.8 v1(82.87,94.76) ; U19.24 v1(84.13,117.2) ; U11.2 v1(84.21,15.13) ; U21.8 v1(106.86,81.76) ; U3.31 v1(22.2,65.99) ; U5.38 v1(44.15,89.55) ; U4.18 v1(28.16,87.49) ; U23.24 v1(108.14,113.6) ; U1.18 v1(27.83,42.49) ; U17.24 v1(84.13,87.27) ; U18.24 v1(84.13,100.37) ; U16.24 v1(84.13,74.6) ; C7.1 v1(78.68,31) ; U19.8 v1(82.87,107.76) ; U16.8 v1(82.87,65.16)
  VCC1 w0.4: D1.A 99.2,60 ; D1.A 97.34,60 ; D1.A 98.27,59.07 ; D1.A 98.27,60.93 ; L6.1 101.5,11.01 ; L6.1 101.5,9.15 ; L6.1 102.43,10.08 ; L6.1 100.57,10.08 ; 6.03,91.62 J1.29 ; J1.29 7,92.59 ; J1.29 7.97,91.62 ; J1.29 7,90.65 ; 6.03,94.16 J1.30 ; J1.30 7,95.13 ; J1.30 7,93.19 ; J1.30 7.97,94.16 ; 20.49,97.5 U7.8 ; U7.8 22.25,97.5 ; U7.8 21.37,98.38 ; U7.8 21.37,96.62 ; 11.11,94.16 J1.62 ; J1.62 12.08,93.19 ; J1.62 12.08,95.13 ; J1.62 13.05,94.16 ; 100.57,30 L4.1 ; L4.1 102.43,30 ; L4.1 101.5,29.07 ; L4.1 101.5,30.93 ; D3.A 111.2,55 ; D3.A 109.34,55 ; D3.A 110.27,54.07 ; D3.A 110.27,55.93 ; 115.34,52.5 D4.A ; D4.A 116.27,53.43 ; D4.A 116.27,51.57 ; D4.A 117.2,52.5 ; D2.A 105.2,57.5 ; D2.A 104.27,58.43 ; D2.A 103.34,57.5 ; D2.A 104.27,56.57 ; U7.7 22.25,100.04 ; U7.7 21.37,100.92 ; U7.7 21.37,99.16 ; U7.7 20.49,100.04 ; 38.37,50.67 U2.24 ; U2.24 38.37,52.33 ; U2.24 39.2,51.5 ; U2.24 37.54,51.5
  VCC2 w0.4: D1.A 99.2,60 ; D1.A 97.34,60 ; D1.A 98.27,60.93 ; D1.A 98.27,59.07 ; 7,90.65 J1.29 ; J1.29 7.97,91.62 ; J1.29 7,92.59 ; J1.29 6.03,91.62 ; D4.A 116.27,53.43 ; D4.A 117.2,52.5 ; D4.A 116.27,51.57 ; D4.A 115.34,52.5 ; 7,93.19 J1.30 ; J1.30 6.03,94.16 ; J1.30 7.97,94.16 ; J1.30 7,95.13 ; U7.7 21.37,100.92 ; U7.7 22.25,100.04 ; U7.7 20.49,100.04 ; U7.7 21.37,99.16 ; J1.62 13.05,94.16 ; J1.62 12.08,93.19 ; J1.62 11.11,94.16 ; J1.62 12.08,95.13 ; 109.34,55 D3.A ; D3.A 111.2,55 ; D3.A 110.27,55.93 ; D3.A 110.27,54.07 ; D2.A 105.2,57.5 ; D2.A 104.27,58.43 ; D2.A 104.27,56.57 ; D2.A 103.34,57.5 ; L4.1 102.43,30 ; L4.1 100.57,30 ; L4.1 101.5,30.93 ; L4.1 101.5,29.07 ; 37.54,51.5 U2.24 ; U2.24 38.37,52.33 ; U2.24 38.37,50.67 ; U2.24 39.2,51.5 ; 20.49,97.5 U7.8 ; U7.8 21.37,96.62 ; U7.8 21.37,98.38 ; U7.8 22.25,97.5 ; L6.1 101.5,11.01 ; L6.1 100.57,10.08 ; L6.1 101.5,9.15 ; L6.1 102.43,10.08
  BOTTOM w0.4: C22.1 v1(104.53,71.5) ; C1.1 v1(25,36.14) ; C26.1 v1(104.78,97.5) ; C2.1 v1(38.5,48) ; C27.1 v1(104.53,110.5) ; C25.1 v1(80.45,97.5) ; v1(104.78,84.7) 105.91,84.7 C24.1 ; C23.1 v1(80.45,84.5) ; C4.1 v1(25,80.95) ; v1(24.7,59.78) 24.7,60.82 C3.1 ; C28.1 v1(80.78,110.5) ; C21.1 v1(80.45,71.5)
A0: length 15
  TOP w0.15: v1(17.69,83.79) 18.22,84.32 U4.36
  BOTTOM w0.15: v1(17.69,83.79) 17.69,79.45 J1.54
A1: length 13.9
  TOP w0.15: U4.35 v1(16.96,84.95)
  BOTTOM w0.15: J1.55 16.96,81.26 v1(16.96,84.95)
A2: length 13.2
  TOP w0.15: U4.33 v1(15.93,86.22)
  BOTTOM w0.15: v1(15.93,86.22) 15.93,82.77 J1.56
A3: length 11.7
  TOP w0.15: U4.32 17.19,86.86 v1(17.09,86.95)
  BOTTOM w0.15: J1.57 14.29,83.67 14.29,85.69 15.56,86.95 v1(17.09,86.95)
A4: length 9.9
  TOP w0.15: J1.58 16.21,88.13 U4.30
A5: length 9.1
  TOP w0.15: J1.59 14.3,88.76 U4.29
A6: length 8.6
  TOP w0.15: U4.27 13.03,90.03 J1.60
A7: length 8.6
  TOP w0.15: J1.61 13.03,90.67 U4.26
A8: length 15.3
  TOP w0.15: J1.13 8.31,52.29 15.22,52.29 18.76,55.83 U3.47
A9: length 14.5
  TOP w0.15: U3.46 15.71,56.47 14.07,54.83 8.31,54.83 J1.14
A10: length 13.9
  TOP w0.15: U3.44 14.18,57.74 13.81,57.37 8.31,57.37 J1.15
A11: length 14.2
  TOP w0.15: U3.43 15.51,58.37 14.27,59.61 8.01,59.61 J1.16
A12: length 13.9
  TOP w0.15: U3.41 17.13,59.64 16.86,59.91 13.08,59.91 12.97,60.02 8.12,60.02 J1.17
A13: length 17.3
  TOP w0.15: U3.40 14.06,60.28 v1(13.53,60.82)
  BOTTOM w0.15: v1(13.53,60.82) 13.53,63.68 12.4,64.8 8.12,64.8 J1.18
A14: length 15.2
  TOP w0.15: U3.38 v1(16.79,61.55)
  BOTTOM w0.15: J1.19 8.12,65.1 13.24,65.1 v1(16.79,61.55)
A15: length 16.9
  TOP w0.15: U3.37 19,62.18 18.78,62.41 11.84,62.41 9.51,64.74 9.51,66.25 J1.20
A16: length 8.9
  TOP w0.15: J1.37 13.75,32.33 U1.47
A17: length 8.3
  TOP w0.15: J1.38 12.31,32.97 U1.46
A18: length 76.7
  TOP w0.15: J1.39 12.08,34.64 12.48,34.24 U1.44
  BOTTOM w0.15: J1.39 10.77,37.05 6.7,37.05 5.69,38.07 5.69,48.56 6.83,49.71 8.04,49.71 8.19,49.56 15.55,49.56 18.67,52.67 38.75,52.67 43.58,57.5 43.58,61.78 U2.6
A19: length 57.9
  TOP w0.15: v1(25,34.77) 21.5,34.77 21.41,34.87 U1.43 13.93,34.87 v1(13.83,34.98)
  BOTTOM w0.15: v1(25,34.77) 34.17,34.77 46.88,47.48 46.88,56.96 44.83,59.01 44.83,60.48 U2.5 ; J1.40 13.83,36.53 v1(13.83,34.98)
A20: length 60
  TOP w0.15: U1.41 18.52,36.14 v1(18.09,35.71)
  BOTTOM w0.15: J1.41 17.19,35.71 v1(18.09,35.71) 20.93,32.87 34.48,32.87 47.17,45.57 47.17,57.95 U2.4
A21: length 50.3
  TOP w0.15: U1.40 17.39,36.78 v1(17.29,36.88)
  BOTTOM w0.15: 16.99,43.36 16.99,45.52 23.85,52.38 41.8,52.38 U2.3 ; 16.99,43.36 17.29,43.06 v1(17.29,36.88) ; 16.99,43.36 J1.42
A22: length 66.7
  TOP w0.15: J1.43 11.07,44.89 6.58,44.89 5.69,45.78 5.69,48.65 6.82,49.77 v1(22.92,49.77) 23.65,49.04 23.65,40.29 21.41,38.05 U1.38
  BOTTOM w0.15: U2.2 42.47,50.51 23.65,50.51 v1(22.92,49.77)
A23: length 47.2
  TOP w0.15: U1.37 21.45,38.68 23.35,40.59 23.35,47.71 v1(22.62,48.44) J1.44
  BOTTOM w0.15: U2.1 44.27,49.77 32.42,49.77 31.08,48.44 v1(22.62,48.44)
AEN: length 50.3
  BOTTOM w0.15: J1.47 33.99,56.06 35.63,57.7 38.74,57.7 42.73,61.69 42.73,69.9 45.92,73.09 45.97,73.09 46.88,72.19 46.88,70.16 U2.8
BA0: length 106
  TOP w0.15: v1(35.21,39.42) 35.21,60.34 32.74,62.82 ; v1(31.95,39.42) 31.84,39.32 U1.13 ; 32.74,62.82 32.74,70.3 31.22,71.82 30.8,71.82 30.01,72.62 30.01,74.08 31.21,75.29 ; 32.74,62.82 U3.13 ; U5.6 v1(44.15,109.77) ; 31.21,75.29 31.21,77.11 31,77.33 U4.2 ; 31.21,75.29 37.34,75.29 37.53,75.48 39.21,75.48 39.4,75.29 v1(44.88,75.29)
  BOTTOM w0.15: v1(44.88,75.29) 43.19,76.97 43.19,108.81 v1(44.15,109.77) ; v1(35.21,39.42) v1(31.95,39.42)
BA1: length 125
  TOP w0.15: U5.7 v1(42.88,113.81) ; v1(32.01,63.55) 31.91,63.45 U3.14 ; v1(33.9,63.55) 34.71,63.55 35.14,63.12 38.23,63.12 39.24,62.1 39.24,38.75 31.75,31.25 28.73,31.25 27.07,32.9 27.07,38.55 28.47,39.95 U1.14 ; U4.3 32.25,77.97 v1(34.2,76.03) v1(42.88,76.03)
  BOTTOM w0.15: v1(42.88,113.81) v1(42.88,76.03) ; v1(32.01,63.55) v1(33.9,63.55) 34.63,64.28 34.63,74.78 34.2,75.21 v1(34.2,76.03)
BA2: length 132.5
  TOP w0.15: U1.16 28.52,41.22 26.77,39.48 26.77,32.73 28.93,30.57 32.71,30.57 41.22,39.08 41.22,65.18 38.79,67.62 v1(37.06,67.62) 37.06,66.8 34.98,64.72 v1(33.77,64.72) ; U5.8 v1(41.61,113.81) ; U4.5 34.7,79.24 35.75,78.19 v1(41.61,78.19) ; U3.16 v1(31.71,64.72)
  BOTTOM w0.15: v1(41.61,113.81) v1(41.61,78.19) 41.61,71.17 38.05,67.62 v1(37.06,67.62) ; v1(31.71,64.72) v1(33.77,64.72)
BA3: length 90.8
  TOP w0.15: v1(33.17,80.02) 33.03,79.87 U4.6 ; U5.9 v1(40.34,109.95) ; U3.17 v1(28.16,65.36) 27.43,64.62 27.43,51.18 28.45,50.17 29.08,50.17 32.38,46.87 32.38,43.24 31,41.86 U1.17
  BOTTOM w0.15: v1(40.34,109.95) 39.57,109.95 34.24,104.62 34.24,97.05 33.21,96.02 33.21,90.11 33.91,89.41 33.91,80.75 v1(33.17,80.02) 33.17,68.25 31.65,66.72 29.53,66.72 v1(28.16,65.36)
BA4: length 50.4
  TOP w0.15: v1(29.71,75.09) 29.71,72.45 31.23,70.92 31.65,70.92 32.44,70.13 32.44,67.57 31.65,66.77 31.06,66.77 30.91,66.63 U3.19 28.27,66.63 27.13,65.48 27.13,51 29.16,48.97 29.8,48.97 32.08,46.68 32.08,44.02 31.19,43.13 U1.19 ; U4.8 v1(31.65,81.14)
  BOTTOM w0.15: v1(31.65,81.14) 29.71,79.2 v1(29.71,75.09)
BA5: length 48
  TOP w0.15: v1(25.02,67.76) 25.02,66.94 25.43,66.53 25.43,45.92 27.59,43.76 U1.20 ; U3.20 28,67.26 v1(27.51,67.76) ; v1(27.51,70.07) 27.43,70.15 27.43,80.89 28.32,81.78 U4.9
  BOTTOM w0.15: v1(27.51,70.07) v1(27.51,67.76) v1(25.02,67.76)
BA6: length 45.7
  TOP w0.15: v1(27.51,47) 26.77,47.73 26.77,68.53 ; U4.11 28.55,83.05 26.77,81.27 26.77,68.53 ; 26.77,68.53 U3.22 ; U1.22 27.65,45.03 v1(27.51,44.89)
  BOTTOM w0.15: v1(27.51,47) v1(27.51,44.89)
BA7: length 49.2
  TOP w0.15: v1(28.54,71.35) 28.54,69.47 28.84,69.17 U3.23 ; U4.12 28.52,83.68 25.75,80.92 v1(25.75,71.35) 25.75,47.7 27.78,45.67 U1.23
  BOTTOM w0.15: v1(28.54,71.35) v1(25.75,71.35)
BD0: length 14.6
  TOP w0.15: U5.25 32.93,97.69 31.72,96.49 29.23,96.49 28.59,95.85 28.59,90.97 28.89,90.67 U4.23
BD1: length 18.2
  TOP w0.15: U5.24 28.59,98.96 28.07,98.44 28.07,90.55 28.59,90.03 U4.22
BD2: length 17.9
  TOP w0.15: U5.23 v1(32.08,100.23) ; v1(32.08,88.95) 31.89,88.76 U4.20
  BOTTOM w0.15: v1(32.08,88.95) v1(32.08,100.23)
BD3: length 19.9
  TOP w0.15: U4.19 v1(32.91,88.13) ; U5.22 v1(32.91,101.5)
  BOTTOM w0.15: v1(32.91,88.13) v1(32.91,101.5)
BD4: length 22.4
  TOP w0.15: U5.21 v1(31.35,102.77) ; U4.17 v1(31.35,86.86)
  BOTTOM w0.15: v1(31.35,86.86) v1(31.35,102.77)
BD5: length 27.5
  TOP w0.15: U4.16 28.59,86.22 28.45,86.37 28.22,86.37 27.43,87.16 27.43,102.41 28.72,103.7 29.8,103.7 29.91,103.8 33.41,103.8 33.64,104.04 U5.20
BD6: length 30.3
  TOP w0.15: U4.14 28.59,84.95 28.5,84.86 27.64,84.86 27.13,85.36 27.13,102.58 28.65,104.1 31.12,104.1 32.33,105.31 U5.19
BD7: length 33.1
  TOP w0.15: U5.18 29.07,106.58 26.53,104.04 26.53,85.46 27.67,84.32 U4.13
BD8: length 22.3
  TOP w0.15: U3.2 31.92,55.83 32.68,55.07 32.68,39.08 32.28,38.68 U1.12
BD9: length 23.7
  TOP w0.15: U1.11 30.91,38.05 31.06,38.19 32.35,38.19 32.98,38.83 32.98,55.31 31.96,56.32 31.06,56.32 30.91,56.47 U3.3
BD10: length 32.1
  TOP w0.15: v1(28.16,51.54) 28.16,57.38 28.52,57.74 U3.5 ; U1.9 v1(27.81,36.78)
  BOTTOM w0.15: v1(28.16,51.54) 23.54,51.54 21.88,49.89 21.88,48.13 26.77,43.24 26.77,37.81 v1(27.81,36.78)
BD11: length 27.2
  TOP w0.15: U1.8 31.5,36.14 33.28,37.92 33.28,56.59 31.5,58.37 U3.6
BD12: length 29.4
  TOP w0.15: U3.8 31.04,59.64 33.58,57.1 33.58,37.41 31.04,34.87 U1.6
BD13: length 30.9
  TOP w0.15: U1.5 30.96,34.24 33.88,37.16 33.88,57.36 30.96,60.28 U3.9
BD14: length 33.7
  TOP w0.15: U3.11 31.01,61.55 34.18,58.37 34.18,36.14 31.01,32.97 U1.3
BD15: length 35.1
  TOP w0.15: U1.2 30.93,32.33 34.48,35.89 34.48,58.63 30.93,62.18 U3.12
BNC2: length 20.3
  TOP w0.15: C5.1 112.73,29.5 111.5,30.73 J2.1
  BOTTOM w0.15: L1.2 109,35 J2.1
BNC3: length 22.4
  TOP w0.15: J3.1 105.04,18.5 L2.2 ; C6.1 v1(111.5,10)
  BOTTOM w0.15: v1(111.5,10) J3.1
BRD: length 70.2
  TOP w0.15: U5.73 56.62,112.93 54.95,114.61 54.95,116.91 54.59,117.26 46.46,117.26 46.05,116.85 46.05,114.36 45.95,114.27 45.95,96.77 40.88,91.69 v1(40.88,85.31)
  BOTTOM w0.15: v1(40.88,85.31) 40.88,74.33 U2.16
BRESET: length 45.4
  TOP w0.15: v1(39.28,106.68) 39.28,109.15 37.41,111.03 35.13,111.03 34.66,111.5 34.66,113.58 35.27,114.2 U5.12
  BOTTOM w0.15: v1(39.28,106.68) 39.28,90.23 37.49,88.44 37.49,75.23 U2.15
BWR: length 52.9
  TOP w0.15: v1(61.4,85.31) 61.4,88.49 61.71,88.8 U5.54 ; v1(61.4,78.39) 62.55,78.39 67.38,73.56 67.38,72.61 65.31,70.55 39.64,70.55 U2.17
  BOTTOM w0.15: v1(61.4,85.31) v1(61.4,78.39)
D0: length 59.4
  TOP w0.15: U4.37 22.51,83.68 23.53,82.67 23.53,70.03 v1(22.66,69.17) U3.26
  BOTTOM w0.15: v1(22.66,69.17) 21.34,69.17 19.67,67.49 6.79,67.49 5.39,68.89 5.39,87.47 J1.28
D1: length 34.8
  TOP w0.15: U3.27 19.38,68.53 19.09,68.83 19.09,71.01 23.23,75.15 23.23,82.51 22.59,83.14 21.5,83.14 21.41,83.05 U4.38 19,83.05 18.84,82.88 10.66,82.88 J1.27
D2: length 33.8
  TOP w0.15: U3.29 19.04,67.26 18.79,67.52 18.79,72.21 22.93,76.35 22.93,80.84 22.14,81.63 21.55,81.63 21.41,81.78 U4.40 16.44,81.78 15.64,82.58 8.42,82.58 J1.26
D3: length 39.1
  TOP w0.15: J1.25 8.27,80.19 14.29,80.19 15.24,81.14 U4.41 ; U3.30 19.02,66.63 17.5,68.15 v1(17.5,70.63)
  BOTTOM w0.15: J1.25 10.11,78.35 10.11,71.81 11.64,70.29 16.34,70.29 16.69,70.63 v1(17.5,70.63)
D4: length 29.4
  TOP w0.15: U3.32 19.05,65.36 16.77,67.64 16.77,77.61 16.47,77.91 ; J1.24 8.12,77.8 16.36,77.8 16.47,77.91 ; U4.43 18.43,79.87 16.47,77.91
D5: length 50.7
  TOP w0.15: v1(18.05,71.8) 17.07,72.78 17.07,77.33 18.97,79.24 U4.44 ; J1.23 8.12,77.5 14.18,77.5 16.32,75.36 16.32,67.39 18.98,64.72 U3.33
  BOTTOM w0.15: J1.23 8.91,74.47 8.91,72.57 11.58,69.9 17.9,69.9 18.63,70.63 18.63,71.22 v1(18.05,71.8)
D6: length 30.7
  TOP w0.15: U4.46 18.2,77.97 17.8,77.57 v1(17.8,75.02) ; U3.35 19.01,63.45 15.58,66.88 v1(15.58,75.02) 8.18,75.02 J1.22
  BOTTOM w0.15: v1(17.8,75.02) v1(15.58,75.02)
D7: length 57.8
  TOP w0.15: v1(18.53,77.19) 18.68,77.33 U4.47 ; U3.36 19,62.82 13.99,67.83 13.99,68.3 12.21,70.07 8.23,70.07 J1.21
  BOTTOM w0.15: v1(18.53,77.19) 18.53,86.67 17.4,87.81 6.74,87.81 5.99,87.05 5.99,72.31 J1.21
D8: length 20.3
  TOP w0.15: U1.36 17.23,39.32 14.96,37.05 11.86,37.05 10.71,35.91 10.71,31.83 J1.4
D9: length 19.4
  TOP w0.15: J1.5 10.11,33.77 10.11,37.77 11.74,39.4 14.97,39.4 15.52,39.95 U1.35
D10: length 17.7
  TOP w0.15: J1.6 9.51,35.71 9.51,37.69 11.53,39.7 13.29,39.7 14.81,41.22 U1.33
D11: length 16.7
  TOP w0.15: J1.7 8.61,37.35 8.61,38.91 11.56,41.86 U1.32
D12: length 15.3
  TOP w0.15: U1.30 14.63,43.13 v1(14.13,42.63)
  BOTTOM w0.15: v1(14.13,42.63) 13.31,42.63 12.82,42.13 10.85,42.13 J1.8
D13: length 14.5
  TOP w0.15: U1.29 14.21,43.76 12.69,42.24 8.42,42.24 J1.9
D14: length 13.9
  TOP w0.15: J1.10 8.01,44.37 12.76,44.37 13.42,45.03 U1.27
D15: length 14.4
  TOP w0.15: J1.11 8.27,47.17 15.21,47.17 16.71,45.67 U1.26
DATA: length 20.4
  TOP w0.15: U5.14 v1(38.55,111.66)
  BOTTOM w0.15: U7.1 29,98.5 29.93,99.43 29.93,103.03 v1(38.55,111.66)
DCLK: length 24.8
  TOP w0.15: U7.2 30.23,101.27 30.23,102.71 31.02,103.5 34.77,103.5 34.87,103.41 37.43,103.41 40.32,106.3 40.32,107.95 39.59,108.68 39.59,113.03 39.07,113.55 U5.10
DDIR: length 86.5
  TOP w0.15: 23.68,55.2 23.38,55.5 v1(23.38,58.79) 23.38,59.6 23.83,60.05 23.83,88.96 21.48,91.3 20.25,91.3 ; 23.68,55.2 24.57,54.31 24.57,43.69 25.73,42.53 25.73,34.36 23.07,31.7 U1.48 ; 23.68,55.2 23.68,55.2 U3.48
  BOTTOM w0.15: U2.20 27.74,61.66 24.87,58.79 v1(23.38,58.79)
DEN: length 71.1
  TOP w0.15: 29.75,31.7 31.16,31.7 37.25,37.79 37.25,58 U2.21 ; U4.24 v1(33.94,91.3)
  BOTTOM w0.15: U2.21 39.55,60.3 39.55,61.82 38.43,62.93 38.26,62.93 34.93,66.26 34.93,90.31 v1(33.94,91.3)
DHEN: length 9.3
  TOP w0.15: 29.75,55.2 31.5,55.2 v1(31.65,55.05)
  BOTTOM w0.15: v1(31.65,55.05) 36.84,55.05 U2.22
FPGA: length 30
  TOP w0.15: U5.30 v1(38.55,91.34)
  BOTTOM w0.15: U2.18 36.84,66.74 35.82,67.76 35.82,88.61 v1(38.55,91.34)
GAIN: length 120.2
  TOP w0.15: 77.04,46.14 86.98,46.14 87.32,45.8 87.32,44.74 86.71,44.13 U10.6 ; 77.04,46.14 74.58,48.6 72.49,48.6 68.43,52.66 68.43,73.67 60.94,81.17 43.97,81.17 39.66,85.48 39.66,92.61 38.38,93.88 U5.28 ; 77.04,46.14 76.74,45.84 76.74,31.32 81.18,26.88 86.35,26.88 87.23,25.99 87.23,25.01 86.44,24.21 U13.6
HS: length 33.1
  TOP w0.15: U5.29 v1(38.55,92.61)
  BOTTOM w0.15: U2.19 35.52,67.05 35.52,89.58 v1(38.55,92.61)
LED1: length 31.3
  TOP w0.15: D1.C 89.06,60 89.06,60.9 88.79,60.9 88.79,60 88.51,60 88.51,60.9 88.23,60.9 88.23,60 87.96,60 87.96,60.9 87.68,60.9 87.68,60 87.4,60 87.4,60.9 87.12,60.9 87.12,60 86.85,60 86.85,60.9 86.57,60.9 86.57,60 86.29,60 86.29,60.9 86.02,60.9 86.02,60 85.74,60 85.74,60.9 85.46,60.9 85.46,60 85.19,60 85.19,60.9 84.91,60.9 84.91,60 84.63,60 84.63,60.9 84.35,60.9 84.35,60 84.08,60 84.08,60.9 83.8,60.9 83.8,60 R1.2
LED2: length 31.3
  TOP w0.15: R2.2 83.71,57.5 83.71,58.5 83.99,58.5 83.99,57.5 84.27,57.5 84.27,58.5 84.54,58.5 84.54,57.5 84.82,57.5 84.82,58.5 85.1,58.5 85.1,57.5 85.38,57.5 85.38,58.5 85.65,58.5 85.65,57.5 85.93,57.5 85.93,58.5 86.21,58.5 86.21,57.5 86.48,57.5 86.48,58.5 86.76,58.5 86.76,57.5 D2.C
LED3: length 31.3
  TOP w0.15: D3.C 85.13,55 85.13,56 84.85,56 84.85,55 84.57,55 84.57,56 84.3,56 84.3,55 84.02,55 84.02,56 83.74,56 83.74,55 R3.2
LED4: length 31.3
  TOP w0.15: R4.2 D4.C
MCLK: length 49.8
  TOP w0.15: v1(31.35,83.58) 36.18,83.58 38.44,85.84 38.44,89.47 37.84,90.07 U5.31
  BOTTOM w0.15: J1.52 18.07,68.76 21.4,72.09 31.46,72.09 31.97,72.59 31.97,73.56 31.18,74.35 29.37,74.35 28.97,74.75 28.97,81.2 v1(31.35,83.58)
MEMORY.RA0: length 184.5
  TOP w0.15: 79.58,92.92 79.58,93.97 79.69,93.86 79.69,91.7 79.58,91.59 79.58,90.41 79.69,90.3 79.69,87.4 81.48,85.61 81.48,83.6 81.06,83.18 81.06,80.94 80.96,80.84 80.96,78.69 81.06,78.59 ; 79.58,92.92 79.58,101.03 79.69,101.14 79.69,103.3 79.58,103.41 79.58,104 79.06,104.52 U19.5 79.06,107.5 77.72,108.83 77.72,112.16 77.03,112.84 77.03,114.03 77.15,114.14 77.15,116.3 77.03,116.41 v1(77.03,117.57) ; 79.58,92.92 79.2,92.92 U18.5 ; U22.5 103.06,92.39 103.86,91.59 109.92,91.59 109.92,91.68 ; 109.92,91.68 110.14,91.68 110.14,90.38 110.04,90.28 110.04,88.16 110.14,88.06 v1(110.14,87.23) 110.14,86.01 107.22,83.09 105.1,83.09 103.06,81.05 U21.5 ; 109.92,91.68 109.92,91.59 110.04,91.7 110.04,96.48 108.87,97.65 108.87,101.06 108.77,101.16 108.77,103.17 108.23,103.7 103.86,103.7 103.06,104.52 U23.5 ; U5.79 58.12,117.34 62.18,117.34 62.56,116.95 62.56,114.65 63.65,113.56 66.93,113.56 67.43,114.06 v1(67.43,117.57) ; 103.36,69.89 v1(111.25,69.89) ; 103.36,69.89 103.06,69.59 U20.5 ; 103.36,69.89 102.48,70.77 v1(79.06,70.77) U16.5 ; 81.06,78.59 79.85,78.59 79.06,79.39 U17.5 ; 81.06,78.59 81.06,77.38 80.96,77.28 80.96,75.21 v1(79.06,73.31)
  BOTTOM w0.15: v1(67.43,117.57) v1(77.03,117.57) ; v1(111.25,69.89) 111.25,72.96 110.91,73.3 110.91,79.45 111.55,80.09 111.55,85.82 v1(110.14,87.23) ; v1(79.06,73.31) v1(79.06,70.77)
MEMORY.RA1: length 202.4
  TOP w0.15: 78.31,72.53 77.78,72.01 U16.4 77.78,66.4 76.98,65.59 72.78,65.59 72.27,66.1 72.27,70.33 70.24,72.36 70.24,84.24 66.56,87.92 66.56,92.64 65.95,93.25 62.7,93.25 53.28,102.67 v1(53.28,108.27) ; 78.31,72.53 78.31,75.03 78.42,75.14 78.42,77.63 77.78,78.27 U17.4 ; 78.31,72.53 80.77,72.53 81.59,71.71 v1(102,71.71) ; U19.4 77.78,104.59 ; 77.78,104.59 77.78,104.07 78.42,103.44 78.42,101.16 78.52,101.06 78.52,98.47 77.57,97.52 77.57,94.26 77.78,94.05 U18.4 ; 77.78,104.59 74.75,104.59 74.61,104.73 74.61,106.86 74.5,106.97 v1(74.5,109.43) ; v1(101.77,81.4) 101.78,81.38 U21.4 ; v1(101.68,107.4) 101.68,105.88 U23.4 ; U20.4 v1(101.78,69.39) ; U5.78 v1(59.39,113.81) ; U22.4 v1(101.78,95.19)
  BOTTOM w0.15: 70.97,109.43 v1(74.5,109.43) ; 70.97,109.43 70.8,109.6 62.82,109.6 59.39,113.03 v1(59.39,113.81) ; 70.97,109.43 70.97,108.93 70.18,108.13 68.56,108.13 68.43,108.27 v1(53.28,108.27) ; v1(101.68,107.4) 101.78,107.29 v1(101.78,95.19) 101.77,95.17 v1(101.77,81.4) 101.77,80.58 101.5,80.32 101.5,73.02 102,72.52 v1(102,71.71) 101.78,71.49 v1(101.78,69.39)
MEMORY.RA2: length 192.6
  TOP w0.15: v1(77.01,78.14) 76.52,78.63 U17.3 ; 73.02,71.32 73.32,71.62 v1(77.01,71.62) ; 73.02,71.32 70.84,73.51 70.84,84.37 69.9,85.31 69.9,96.18 70.2,96.48 v1(70.2,97.29) 70.2,108.46 v1(69.79,108.87) ; 73.02,71.32 73.02,69.22 ; U16.3 76.52,68.08 75.37,69.22 73.02,69.22 ; U20.3 100.52,69.1 v1(100.3,69.31) v1(94.55,69.31) ; U19.3 76.52,109.57 v1(74.19,111.9) ; U23.3 v1(100.52,107.76) ; 73.02,69.22 v1(73.02,66.42) ; v1(100.3,94.4) 100.3,92.99 U22.3 ; U5.77 v1(60.66,113.81) ; U18.3 v1(76.52,97.29) ; U21.3 v1(100.52,82.56)
  BOTTOM w0.15: v1(74.19,111.9) 62.57,111.9 v1(60.66,113.81) 59.93,114.54 58.87,114.54 58.36,114.03 58.36,113.31 62.8,108.87 v1(69.79,108.87) ; v1(100.52,107.76) 100.52,104.29 101.03,103.77 101.03,95.13 v1(100.3,94.4) 100.52,94.19 v1(100.52,82.56) 98.91,82.56 98.51,82.17 98.51,80.7 100.3,78.92 v1(100.3,69.31) ; v1(73.02,66.42) 92.9,66.42 94.55,68.08 v1(94.55,69.31) ; v1(77.01,78.14) v1(77.01,71.62) ; v1(76.52,97.29) v1(70.2,97.29)
MEMORY.RA3: length 151.9
  TOP w0.15: U16.2 75.25,68.25 75,68.49 v1(74.19,68.49) ; 98.5,93.22 98.61,93.1 98.61,91.7 98.5,91.59 98.5,90.8 98.89,90.41 100.91,90.41 101.15,90.16 101.15,85.58 99.25,83.68 v1(99.25,81.76) U21.2 ; 98.5,93.22 98.5,95.22 v1(98.28,95.43) ; 98.5,93.22 98.81,93.22 U22.2 ; U19.2 v1(75.25,108.27) 75.25,110.07 74.85,110.47 74.26,110.47 73.75,109.96 73.75,108.02 73.45,107.72 73.45,104.64 74.09,104 75.13,104 75.88,103.25 75.88,100.3 75.05,99.47 75.05,94.24 75.25,94.05 U18.2 75.25,91.52 74.57,90.84 v1(73.75,90.84) ; v1(92.49,68.49) v1(99.25,68.49) U20.2 ; U5.76 v1(61.93,113.74) ; v1(75.25,81.4) U17.2 ; v1(98.28,100.37) 98.61,100.7 98.61,103.67 99.25,104.31 U23.2
  BOTTOM w0.15: v1(73.75,90.84) 72.94,90.84 71.99,89.89 71.99,82.29 72.88,81.4 74.19,81.4 ; v1(92.49,68.49) 91.67,68.49 91.42,68.23 75.26,68.23 75,68.49 v1(74.19,68.49) 74.19,81.4 ; v1(99.25,81.76) 101.03,79.97 101.03,69 100.53,68.49 v1(99.25,68.49) ; v1(61.93,113.74) 62.74,112.93 74.23,112.93 75.25,111.91 v1(75.25,108.27) ; 74.19,81.4 v1(75.25,81.4) ; v1(98.28,95.43) v1(98.28,100.37)
MEMORY.RA4: length 278.9
  TOP w0.15: U16.32 73.97,75.83 74.78,75.03 75.64,75.03 75.88,75.28 75.88,77.26 74.61,78.53 74.61,80.84 74.51,80.94 v1(74.51,82.56) ; U21.32 97.38,89.22 97.24,89.35 v1(97.24,91.08) ; U20.32 97.97,77.5 98.48,78 104.21,78 104.96,78.75 104.96,80.86 104.84,80.97 104.84,81.77 105.86,82.79 109.61,82.79 111.19,84.38 111.19,90.15 111.45,90.41 114.88,90.41 115.12,90.16 115.12,87.15 115.8,86.47 116.55,86.47 118.58,88.5 118.58,106.92 116.04,109.46 114.37,109.46 113.73,110.1 113.73,114.03 113.85,114.14 113.85,116.38 111.32,118.9 44.01,118.9 43.53,118.43 v1(42.72,118.43) ; v1(97.02,114.22) 97.02,115.03 97.21,115.22 U23.32 ; U19.32 73.97,113.83 72.72,112.58 v1(72.72,110.39) 72.72,101.03 73.02,100.73 ; 73.02,100.73 73.75,100.73 73.97,100.95 U18.32 ; 73.02,100.73 v1(73.02,89.22) U17.32 ; v1(67.05,110.39) U5.71 v1(55.04,110.39) ; v1(97.02,105.03) v1(97.02,102.22) U22.32
  BOTTOM w0.15: v1(74.51,82.56) 74.51,85.55 75.66,86.7 76.74,86.7 77.25,87.2 77.25,88.92 ; 77.25,88.92 95.97,88.92 97.24,90.19 v1(97.24,91.08) 97.24,102 v1(97.02,102.22) ; 77.25,88.92 76.95,89.22 v1(73.02,89.22) ; v1(55.04,110.39) 48.14,110.39 45.22,113.31 45.22,117.79 44.58,118.43 v1(42.72,118.43) ; v1(67.05,110.39) v1(72.72,110.39) ; v1(97.02,114.22) v1(97.02,105.03)
MEMORY.RA5: length 178.1
  TOP w0.15: 95.86,99.94 96.16,99.64 98.61,99.64 99.25,100.27 U22.31 ; 95.86,99.94 v1(95.86,105.03) ; 95.86,99.94 95.18,99.26 95.18,83.85 95.94,83.08 v1(95.94,80.11) ; 72.51,84.93 v1(77.85,84.93) ; 72.51,84.93 72.51,87.73 ; 72.51,84.93 72.51,77.8 72.91,77.41 74.44,77.41 75.25,76.61 U16.31 ; U19.31 74.65,115.22 74.5,115.37 74.5,115.66 ; 74.5,115.66 74.5,116.41 74.61,116.3 74.61,113.86 73.45,112.71 73.45,108.92 73.16,108.61 73.16,104.47 73.92,103.7 74.42,103.7 75.25,102.89 U18.31 ; 74.5,115.66 74.5,116.31 74.4,116.41 73.55,116.41 71.39,114.25 v1(71.39,111.12) 71.39,88.86 72.51,87.73 ; 72.51,87.73 75.03,87.73 75.25,87.95 U17.31 ; U20.31 v1(99.25,74.6) ; U5.70 66.9,109.12 67.78,110.01 67.78,110.74 67.4,111.12 v1(62.81,111.12) ; v1(97.35,86.41) 99.25,88.31 U21.31 ; v1(95.86,113.43) 98.74,113.43 99.25,113.93 U23.31
  BOTTOM w0.15: v1(95.94,80.11) 97.78,80.11 98.08,80.41 ; v1(99.25,74.6) 99.25,79.24 98.08,80.41 ; v1(77.85,84.93) 77.85,87.41 78.74,88.3 89.36,88.3 91.25,86.41 v1(97.35,86.41) 98.08,85.68 98.08,80.41 ; v1(95.86,105.03) v1(95.86,113.43) ; v1(62.81,111.12) v1(71.39,111.12)
MEMORY.RA6: length 168.2
  TOP w0.15: 96.21,85.98 v1(96.21,90.25) 95.48,90.99 95.48,96.64 98.14,99.31 98.93,99.31 v1(100.22,100.6) 100.22,101.92 U22.30 ; 96.21,85.98 96.51,85.68 98.24,85.68 100.52,87.95 U21.30 ; 96.21,85.98 95.91,85.68 95.91,84.15 96.68,83.38 96.68,77.8 96.21,77.33 96.21,74.66 97,73.87 99.63,73.87 100.52,74.76 U20.30 ; U17.30 v1(76.52,87.6) 77.15,88.24 77.15,93.84 77.25,93.94 77.25,97.66 76.52,98.39 U18.30 v1(76.52,103.84) ; v1(67.16,107.53) 66.84,107.85 U5.69 62.67,107.85 59.88,105.06 v1(59.88,104.04) ; U16.30 76.52,74.95 76.16,74.6 v1(73.24,74.6) ; v1(76.05,113.23) 76.52,113.7 U19.30 ; U23.30 v1(100.52,113.41) ; v1(73.24,82.13) v1(73.24,78.16)
  BOTTOM w0.15: v1(73.24,82.13) 73.24,87.3 ; 73.24,87.3 72.29,88.26 72.29,89.56 72.69,89.95 95.1,89.95 95.4,90.25 v1(96.21,90.25) ; 73.24,87.3 73.54,87.6 v1(76.52,87.6) ; v1(67.16,107.53) 75.65,107.53 76.05,107.93 v1(76.05,113.23) ; v1(73.24,78.16) v1(73.24,74.6) ; v1(100.22,100.6) 100.22,101.41 99.78,101.85 99.78,112.68 v1(100.52,113.41) ; v1(59.88,104.04) 76.31,104.04 v1(76.52,103.84)
MEMORY.RA7: length 292.1
  TOP w0.15: U21.29 101.78,87.48 103.56,85.7 104.74,85.7 105.13,86.1 105.13,87.44 105.08,87.5 105.08,88.03 104.96,88.14 104.96,90.16 105.2,90.41 108.63,90.41 108.77,90.26 108.77,88.15 109.31,87.61 v1(109.31,86.41) ; v1(94.75,112.6) 100.77,112.6 101.78,113.62 U23.29 ; U20.29 101.78,75.56 99.8,73.57 96.86,73.57 95.21,75.22 95.21,81.04 95.4,81.23 95.4,82.9 94.88,83.43 94.88,107.96 v1(94.95,108.04) 95.77,108.04 96.22,108.49 101.65,108.49 102.41,107.73 102.41,104.62 101.78,103.99 U22.29 ; U17.29 77.78,86.46 78.84,85.41 v1(78.84,81.7) 76.79,81.7 75.88,80.79 75.88,78.22 76.7,77.41 76.98,77.41 77.78,76.61 U16.29 77.78,74.95 76.7,73.87 72.83,73.87 71.44,75.27 71.44,85.68 70.93,86.19 v1(70.93,87) ; v1(69.16,87) 69.16,87.81 69.49,88.14 69.49,95.04 66.21,98.33 63.62,98.33 62.07,99.88 62.07,102.57 ; v1(67.89,105.81) 66.22,105.81 65.72,105.31 U5.67 62.56,105.31 60.91,103.66 60.91,102.97 61.3,102.57 62.07,102.57 ; 62.07,102.57 v1(62.81,102.57) ; U19.29 v1(77.78,113.48) ; U18.29 v1(77.78,100.6) ; v1(83.27,69.27) 82.84,69.7 81.47,69.7 81.08,69.3 81.08,67.97 80.96,67.85 80.96,65.48 82.34,64.09 108.87,64.09 v1(109.6,64.83)
  BOTTOM w0.15: v1(70.93,87) v1(69.16,87) ; v1(94.95,108.04) 94.95,112.39 v1(94.75,112.6) 92.41,114.94 79.23,114.94 v1(77.78,113.48) 77.78,108.73 74.86,105.81 v1(67.89,105.81) ; v1(83.27,69.27) 82.54,70 78.72,70 78.32,70.4 78.32,77.8 81.06,80.54 81.06,81.73 80.66,82.13 79.27,82.13 v1(78.84,81.7) ; v1(109.6,64.83) 109.6,69.66 110.95,71.01 110.95,72.36 110.61,72.7 110.61,80.65 111.25,81.29 111.25,85.27 110.11,86.41 v1(109.31,86.41) ; v1(62.81,102.57) 63.74,103.5 74.88,103.5 v1(77.78,100.6)
MEMORY.RA8: length 223.3
  TOP w0.15: v1(102.84,87.53) 102.84,89.01 U21.28 ; U5.66 67.66,104.04 69.06,105.44 69.06,109.2 69.95,110.09 70.66,110.09 ; U22.28 102.84,102.01 v1(102.84,100.53) ; 70.66,110.09 v1(70.66,113.96) 73.7,117 75.13,117 75.88,116.25 75.88,114.13 75.31,113.57 75.31,112.4 77.12,110.59 77.12,108.16 78.42,106.86 78.42,104.27 79.06,103.63 U18.28 ; 70.66,110.09 70.96,109.79 70.96,92.91 70.2,92.16 70.2,86.02 71.14,85.08 71.14,75.04 73.04,73.14 v1(76.28,73.14) ; v1(86.14,73.78) 87.08,72.84 96.61,72.84 96.81,73.04 101.23,73.04 v1(102.53,74.34) 103.06,74.86 U20.28 ; U23.28 103.06,111.97 v1(102.54,111.46) ; U17.28 79.06,87.52 v1(78.83,87.3) ; v1(79.28,111.97) 79.06,112.19 U19.28 ; U16.28 v1(79.06,74.55)
  BOTTOM w0.15: v1(79.28,111.97) 79.28,109.77 74.58,105.08 67.56,105.08 67.16,105.47 67.16,106.14 67.56,106.54 75.13,106.54 76.78,108.19 76.78,113.57 76.38,113.96 v1(70.66,113.96) ; v1(78.83,87.3) 78.83,82.73 ; 78.83,82.73 80.6,82.73 81.36,81.97 81.36,74.85 81.06,74.55 ; 78.83,82.73 78.44,82.73 76.28,80.57 v1(76.28,73.14) ; v1(102.53,74.34) 102.53,77.99 103.49,78.94 103.49,83.35 102.84,84 v1(102.84,87.53) v1(102.84,100.53) 102.84,111.16 v1(102.54,111.46) ; v1(86.14,73.78) 81.83,73.78 81.06,74.55 ; v1(79.06,74.55) 81.06,74.55
